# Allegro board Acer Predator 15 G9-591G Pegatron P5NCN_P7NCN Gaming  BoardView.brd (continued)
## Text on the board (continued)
User.45: list("[Package] TOP" "335.Pkg to Pkg Spacing" "0 MIL [PACKAGE_HEIGHT_MIN]" "2 MIL" "-2.00 MIL" "DRC ERROR CLASS/PACKAGE_TOP" "[Shape] Package Geometry/Place_Bound_Top ((-864.6 4046.87) (-777.58 4231.53))" "[Shape] Package Geometry/Place_Bound_Top ((-833.59 4161.7) (-808.59 4186.7))" list(-833.590000 4161.700000) nil)@@@list("kelly1_pan" "2015/09/04 16:11:31" nil "P143000035-PC" "n3-p5-p7ncn.20")@@@list("jennifer_hsu" "2015/09/07 11:49:47" nil "P143000039-PC" "n3-p5-p7ncn.20") | list("[Package] TOP" "336.Pkg to Pkg Spacing" "0 MIL [PACKAGE_HEIGHT_MIN]" "2 MIL" "-2.00 MIL" "DRC ERROR CLASS/PACKAGE_TOP" "[Shape] Package Geometry/Place_Bound_Top ((-864.6 4046.87) (-777.58 4231.53))" "[Shape] Package Geometry/Place_Bound_Top ((-833.59 4091.7) (-808.59 4116.7))" list(-833.590000 4091.700000) nil)@@@list("kelly1_pan" "2015/09/04 16:11:32" nil "P143000035-PC" "n3-p5-p7ncn.20")@@@list("jennifer_hsu" "2015/09/07 11:49:48" nil "P143000039-PC" "n3-p5-p7ncn.20") | list("[Package] BOTTOM" "370.Pkg to Place Keepin Spacing" "0 MIL [NONE]" "0 MIL" "0.00 MIL" "DRC ERROR CLASS/PACKAGE_BOTTOM" "[Shape] Package Keepin/All ((-897.01 -353.7) (9751.34 6916.7))" "[Shape] Package Geometry/Place_Bound_Bottom ((-826.78 3556.76) (-495.92 3746.25))" list(-824.120000 3556.760000) nil)@@@list("kelly1_pan" "2015/09/04 16:12:11" nil "P143000035-PC" "n3-p5-p7ncn.20")@@@list("jennifer_hsu" "2015/09/07 11:50:24" nil "P143000039-PC" "n3-p5-p7ncn.20") | list("[Electrical] ALL" "240.Propagation Delay" "::0.00 MIL:8000.00 MIL [PROPAGATION_DELAY]" "10131.06 MIL" "" "DRC ERROR CLASS/ALL" "[PinPair] <uTiL>cId71<uTiL>.L2:<uTiL>cId4738<uTiL>.40 ((5552.76 2057.63) (-807.76 4797.41))" " " list(-807.760000 4797.410000) nil)@@@list("kelly1_pan" "2015/09/04 14:32:31" nil "P143000035-PC" "n3-p5-p7ncn.20")@@@list("jennifer_hsu" "2015/09/07 11:47:53" nil "P143000039-PC" "n3-p5-p7ncn.20") | list("[Electrical] ALL" "241.Propagation Delay" "::0.00 MIL:8000.00 MIL [PROPAGATION_DELAY]" "10129.08 MIL" "" "DRC ERROR CLASS/ALL" "[PinPair] <uTiL>cId71<uTiL>.L1:<uTiL>cId4738<uTiL>.42 ((5552.76 2077.63) (-807.76 4777.72))" " " list(-807.760000 4777.720000) nil)@@@list("kelly1_pan" "2015/09/04 14:32:32" nil "P143000035-PC" "n3-p5-p7ncn.20")@@@list("jennifer_hsu" "2015/09/07 11:47:54" nil "P143000039-PC" "n3-p5-p7ncn.20") | list("[Electrical] ALL" "242.Propagation Delay" "::2000 mil:13000 mil [PROPAGATION_DELAY]" "13093.22 MIL" "" "DRC ERROR CLASS/ALL" "[PinPair] <uTiL>cId71<uTiL>.BC29:<uTiL>cId4738<uTiL>.60 ((6170.9 1543.34) (-807.76 4600.56))" " " list(-807.760000 4600.560000) nil)@@@list("kelly1_pan" "2015/09/04 14:32:34" nil "P143000035-PC" "n3-p5-p7ncn.20")@@@list("jennifer_hsu" "2015/09/07 11:47:55" nil "P143000039-PC" "n3-p5-p7ncn.20") | list("[Package] TOP" "337.Pkg to Pkg Spacing" "0 MIL [PACKAGE_HEIGHT_MIN]" "2 MIL" "-2.00 MIL" "DRC ERROR CLASS/PACKAGE_TOP" "[Shape] Package Geometry/Place_Bound_Top ((-787.6 5619.96) (-432.4 5903.82))" "[Shape] Package Geometry/Place_Bound_Top ((-692.5 5729.39) (-667.5 5754.39))" list(-787.600000 5741.890000) nil)@@@list("kelly1_pan" "2015/09/04 16:11:34" nil "P143000035-PC" "n3-p5-p7ncn.20")@@@list("jennifer_hsu" "2015/09/07 11:49:48" nil "P143000039-PC" "n3-p5-p7ncn.20") | list("[Package] BOTTOM" "376.Pkg to Place Keepin Spacing" "0 MIL [NONE]" "153.7 MIL" "-153.70 MIL" "DRC ERROR CLASS/PACKAGE_BOTTOM" "[Shape] Package Keepin/All ((-897.01 -353.7) (9751.34 6916.7))" "[Shape] Package Geometry/Place_Bound_Bottom ((-835.12 7070.4) (-675.12 7230.4))" list(-755.120000 6916.700000) nil)@@@list("kelly1_pan" "2015/09/04 16:12:17" nil "P143000035-PC" "n3-p5-p7ncn.20")@@@list("jennifer_hsu" "2015/09/07 11:50:29" nil "P143000039-PC" "n3-p5-p7ncn.20") | list("[Package] TOP" "315.Pkg to Place Keepin Spacing" "0 MIL [NONE]" "153.7 MIL" "-153.70 MIL" "DRC ERROR CLASS/PACKAGE_TOP" "[Shape] Package Keepin/All ((-897.01 -353.7) (9751.34 6916.7))" "[Shape] Package Geometry/Place_Bound_Top ((-835.12 7070.4) (-675.12 7230.4))" list(-755.120000 6916.700000) nil)@@@list("kelly1_pan" "2015/09/04 16:11:04" nil "P143000035-PC" "n3-p5-p7ncn.20")@@@list("jennifer_hsu" "2015/09/07 11:49:22" nil "P143000039-PC" "n3-p5-p7ncn.20") | list("[Electrical] ALL" "252.Propagation Delay" "::2500.00 MIL:5000.00 MIL [PROPAGATION_DELAY]" "8112.74 MIL" "" "DRC ERROR CLASS/ALL" "[PinPair] <uTiL>cId71<uTiL>.E11:<uTiL>cId4003<uTiL>.43 ((5430.14 1895.26) (-557.0 2864.15))" " " list(-557.000000 2864.150000) nil)@@@list("kelly1_pan" "2015/09/04 14:32:48" nil "P143000035-PC" "n3-p5-p7ncn.20")@@@list("jennifer_hsu" "2015/09/07 11:48:06" nil "P143000039-PC" "n3-p5-p7ncn.20") | list("[Electrical] ALL" "253.Propagation Delay" "::2500.00 MIL:5000.00 MIL [PROPAGATION_DELAY]" "8112.59 MIL" "" "DRC ERROR CLASS/ALL" "[PinPair] <uTiL>cId71<uTiL>.G11:<uTiL>cId4003<uTiL>.42 ((5465.09 1889.57) (-557.0 2844.47))" " " list(-557.000000 2844.470000) nil)@@@list("kelly1_pan" "2015/09/04 16:03:03" nil "P143000035-PC" "n3-p5-p7ncn.20")@@@list("jennifer_hsu" "2015/09/07 11:48:07" nil "P143000039-PC" "n3-p5-p7ncn.20") | list("[Electrical] ALL" "256.Propagation Delay" "::2500.00 MIL:5000.00 MIL [PROPAGATION_DELAY]" "7785.26 MIL" "" "DRC ERROR CLASS/ALL" "[PinPair] <uTiL>cId71<uTiL>.B10:<uTiL>cId4003<uTiL>.34 ((5377.06 1916.63) (-557.0 2686.99))" " " list(-557.000000 2686.990000) nil)@@@list("kelly1_pan" "2015/09/04 16:03:08" nil "P143000035-PC" "n3-p5-p7ncn.20")@@@list("jennifer_hsu" "2015/09/07 11:48:10" nil "P143000039-PC" "n3-p5-p7ncn.20") | list("[Electrical] ALL" "258.Propagation Delay" "::2500.00 MIL:5000.00 MIL [PROPAGATION_DELAY]" "7784.38 MIL" "" "DRC ERROR CLASS/ALL" "[PinPair] <uTiL>cId71<uTiL>.A9:<uTiL>cId4003<uTiL>.33 ((5354.26 1921.65) (-557.0 2667.3))" " " list(-557.000000 2667.300000) nil)@@@list("kelly1_pan" "2015/09/04 16:03:11" nil "P143000035-PC" "n3-p5-p7ncn.20")@@@list("jennifer_hsu" "2015/09/07 11:48:12" nil "P143000039-PC" "n3-p5-p7ncn.20") | list("[Electrical] ALL" "196.Propagation Delay" "::2500.00 MIL:5000.00 MIL [PROPAGATION_DELAY]" "7402.96 MIL" "" "DRC ERROR CLASS/ALL" "[PinPair] <uTiL>cId71<uTiL>.C13:<uTiL>cId4003<uTiL>.31 ((5389.1 1849.94) (-557.0 2627.93))" " " list(-557.000000 2627.930000) nil)@@@list("kelly1_pan" "2015/09/04 14:31:25" nil "P143000035-PC" "n3-p5-p7ncn.20")@@@list("jennifer_hsu" "2015/09/07 11:47:07" nil "P143000039-PC" "n3-p5-p7ncn.20") | list("[Electrical] ALL" "195.Propagation Delay" "::2500.00 MIL:5000.00 MIL [PROPAGATION_DELAY]" "7404.26 MIL" "" "DRC ERROR CLASS/ALL" "[PinPair] <uTiL>cId71<uTiL>.D13:<uTiL>cId4003<uTiL>.30 ((5409.1 1850.94) (-557.0 2608.25))" " " list(-557.000000 2608.250000) nil)@@@list("kelly1_pan" "2015/09/04 14:31:24" nil "P143000035-PC" "n3-p5-p7ncn.20")@@@list("jennifer_hsu" "2015/09/07 11:47:06" nil "P143000039-PC" "n3-p5-p7ncn.20") | list("[Electrical] ALL" "286.Propagation Delay" "::0.00 MIL:5000.00 MIL [PROPAGATION_DELAY]" "7752.66 MIL" "" "DRC ERROR CLASS/ALL" "[PinPair] <uTiL>cId71<uTiL>.AE1:<uTiL>cId4003<uTiL>.28 ((5821.26 2077.63) (-557.0 2568.88))" " " list(-557.000000 2568.880000) nil)@@@list("kelly1_pan" "2015/09/04 16:10:29" nil "P143000035-PC" "n3-p5-p7ncn.20")@@@list("jennifer_hsu" "2015/09/07 11:48:42" nil "P143000039-PC" "n3-p5-p7ncn.20") | list("[Electrical] ALL" "287.Propagation Delay" "::0.00 MIL:5000.00 MIL [PROPAGATION_DELAY]" "7756.98 MIL" "" "DRC ERROR CLASS/ALL" "[PinPair] <uTiL>cId71<uTiL>.AE2:<uTiL>cId4003<uTiL>.27 ((5821.26 2057.63) (-557.0 2549.19))" " " list(-557.000000 2549.190000) nil)@@@list("kelly1_pan" "2015/09/04 16:10:30" nil "P143000035-PC" "n3-p5-p7ncn.20")@@@list("jennifer_hsu" "2015/09/07 11:48:43" nil "P143000039-PC" "n3-p5-p7ncn.20") | list("[Package] TOP" "338.Pkg to Pkg Spacing" "0 MIL [PACKAGE_HEIGHT_MIN]" "2 MIL" "-2.00 MIL" "DRC ERROR CLASS/PACKAGE_TOP" "[Shape] Package Geometry/Place_Bound_Top ((-787.6 5619.96) (-432.4 5903.82))" "[Shape] Package Geometry/Place_Bound_Top ((-552.5 5719.39) (-527.5 5744.39))" list(-432.400000 5731.890000) nil)@@@list("kelly1_pan" "2015/09/04 16:11:35" nil "P143000035-PC" "n3-p5-p7ncn.20")@@@list("jennifer_hsu" "2015/09/07 11:49:49" nil "P143000039-PC" "n3-p5-p7ncn.20") | list("[Package] TOP" "309.Pkg to Place Keepin Spacing" "0 MIL [NONE]" "0 MIL" "0.00 MIL" "DRC ERROR CLASS/PACKAGE_TOP" "[Shape] Package Keepin/All ((-897.01 -353.7) (9751.34 6916.7))" "[Shape] Package Geometry/Place_Bound_Top ((-242.29 6641.71) (92.71 6956.71))" list(-242.290000 6916.700000) nil)@@@list("kelly1_pan" "2015/09/04 16:10:55" nil "P143000035-PC" "n3-p5-p7ncn.20")@@@list("jennifer_hsu" "2015/09/07 11:49:18" nil "P143000039-PC" "n3-p5-p7ncn.20") | list("[Package] BOTTOM" "363.Pkg to Place Keepin Spacing" "0 MIL [NONE]" "0 MIL" "0.00 MIL" "DRC ERROR CLASS/PACKAGE_BOTTOM" "[Shape] Package Keepin/All ((-897.01 -353.7) (9751.34 6916.7))" "[Shape] Package Geometry/Place_Bound_Bottom ((-232.29 6641.71) (82.71 6956.71))" list(-179.680000 6916.700000) nil)@@@list("kelly1_pan" "2015/09/04 16:12:04" nil "P143000035-PC" "n3-p5-p7ncn.20")@@@list("jennifer_hsu" "2015/09/07 11:50:17" nil "P143000039-PC" "n3-p5-p7ncn.20") | list("[Package] BOTTOM" "355.Pkg to Place Keepin Spacing" "0 MIL [NONE]" "0 MIL" "0.00 MIL" "DRC ERROR CLASS/PACKAGE_BOTTOM" "[Shape] Package Keepin/All ((-897.01 -353.7) (9751.34 6916.7))" "[Shape] Package Geometry/Place_Bound_Bottom ((-449.01 143.5) (19.1 1506.1))" list(-117.480000 143.500000) nil)@@@list("kelly1_pan" "2015/09/04 16:11:56" nil "P143000035-PC" "n3-p5-p7ncn.20")@@@list("jennifer_hsu" "2015/09/07 11:50:06" nil "P143000039-PC" "n3-p5-p7ncn.20") | list("[Package] BOTTOM" "375.Pkg to Place Keepin Spacing" "0 MIL [NONE]" "576.2 MIL" "-576.20 MIL" "DRC ERROR CLASS/PACKAGE_BOTTOM" "[Shape] Package Keepin/All ((-897.01 -353.7) (9751.34 6916.7))" "[Shape] Package Geometry/Place_Bound_Bottom ((-835.12 -588.66) (-675.12 -428.66))" list(-117.480000 -353.700000) nil)@@@list("kelly1_pan" "2015/09/04 16:12:16" nil "P143000035-PC" "n3-p5-p7ncn.20")@@@list("jennifer_hsu" "2015/09/07 11:50:28" nil "P143000039-PC" "n3-p5-p7ncn.20") | list("[Package] TOP" "314.Pkg to Place Keepin Spacing" "0 MIL [NONE]" "576.2 MIL" "-576.20 MIL" "DRC ERROR CLASS/PACKAGE_TOP" "[Shape] Package Keepin/All ((-897.01 -353.7) (9751.34 6916.7))" "[Shape] Package Geometry/Place_Bound_Top ((-835.12 -588.66) (-675.12 -428.66))" list(-117.480000 -353.700000) nil)@@@list("kelly1_pan" "2015/09/04 16:11:03" nil "P143000035-PC" "n3-p5-p7ncn.20")@@@list("jennifer_hsu" "2015/09/07 11:49:21" nil "P143000039-PC" "n3-p5-p7ncn.20") | list("[Package] TOP" "319.Pkg to Place Keepin Spacing" "0 MIL [NONE]" "138.64 MIL" "-138.64 MIL" "DRC ERROR CLASS/PACKAGE_TOP" "[Shape] Package Keepin/All ((-897.01 -353.7) (9751.34 6916.7))" "[Shape] Package Geometry/Place_Bound_Top ((-200.18 7055.34) (-10.06 7245.46))" list(-105.130000 6916.700000) nil)@@@list("kelly1_pan" "2015/09/04 16:11:09" nil "P143000035-PC" "n3-p5-p7ncn.20")@@@list("jennifer_hsu" "2015/09/07 11:49:25" nil "P143000039-PC" "n3-p5-p7ncn.20") | list("[Package] TOP" "339.Pkg to Pkg Spacing" "0 MIL [PACKAGE_HEIGHT_MIN]" "2 MIL" "-2.00 MIL" "DRC ERROR CLASS/PACKAGE_TOP" "[Shape] Package Geometry/Place_Bound_Top ((-171.93 5764.29) (111.93 6119.49))" "[Shape] Package Geometry/Place_Bound_Top ((-42.5 5999.39) (-17.5 6024.39))" list(-30.000000 6119.490000) nil)@@@list("kelly1_pan" "2015/09/04 16:11:36" nil "P143000035-PC" "n3-p5-p7ncn.20")@@@list("jennifer_hsu" "2015/09/07 11:49:52" nil "P143000039-PC" "n3-p5-p7ncn.20") | list("[Package] TOP" "340.Pkg to Pkg Spacing" "0 MIL [PACKAGE_HEIGHT_MIN]" "2 MIL" "-2.00 MIL" "DRC ERROR CLASS/PACKAGE_TOP" "[Shape] Package Geometry/Place_Bound_Top ((-171.93 5764.29) (111.93 6119.49))" "[Shape] Package Geometry/Place_Bound_Top ((-42.5 5859.39) (-17.5 5884.39))" list(-30.000000 5764.290000) nil)@@@list("kelly1_pan" "2015/09/04 16:11:37" nil "P143000035-PC" "n3-p5-p7ncn.20")@@@list("jennifer_hsu" "2015/09/07 11:49:53" nil "P143000039-PC" "n3-p5-p7ncn.20") | list("[Package] BOTTOM" "380.Pkg to Place Keepin Spacing" "0 MIL [NONE]" "139.98 MIL" "-139.98 MIL" "DRC ERROR CLASS/PACKAGE_BOTTOM" "[Shape] Package Keepin/All ((-897.01 -353.7) (9751.34 6916.7))" "[Shape] Package Geometry/Place_Bound_Bottom ((-0.18 7055.34) (189.94 7245.46))" list(69.860000 6916.700000) nil)@@@list("kelly1_pan" "2015/09/04 16:12:21" nil "P143000035-PC" "n3-p5-p7ncn.20")@@@list("jennifer_hsu" "2015/09/07 11:50:31" nil "P143000039-PC" "n3-p5-p7ncn.20") | list("[Electrical] ALL" "259.Diffpair Max Uncoupled Length" "200 MIL [DIFFP_UNCOUPLED_LENGTH]" "210.69 MIL" "-10.69 MIL" "DRC ERROR CLASS/ALL" "[PinPair] <uTiL>cId3011<uTiL>.32:<uTiL>cId3020<uTiL>.BL3 ((691.93 2649.6) (40.5 4582.15))" "[PinPair] <uTiL>cId3011<uTiL>.34:<uTiL>cId3020<uTiL>.BK3 ((711.62 2649.6) (71.5 4582.15))" list(71.500000 4582.150000) nil)@@@list("kelly1_pan" "2015/09/04 16:03:12" nil "P143000035-PC" "n3-p5-p7ncn.20")@@@list("jennifer_hsu" "2015/09/07 11:48:13" nil "P143000039-PC" "n3-p5-p7ncn.20") | list("[Package] BOTTOM" "382.Pkg to Place Keepin Spacing" "0 MIL [NONE]" "312.91 MIL" "-312.91 MIL" "DRC ERROR CLASS/PACKAGE_BOTTOM" "[Shape] Package Keepin/All ((-897.01 -353.7) (9751.34 6916.7))" "[Shape] Package Geometry/Place_Bound_Bottom ((399.82 -603.72) (589.94 -413.6))" list(117.480000 -353.700000) nil)@@@list("kelly1_pan" "2015/09/04 16:12:23" nil "P143000035-PC" "n3-p5-p7ncn.20")@@@list("jennifer_hsu" "2015/09/07 11:50:34" nil "P143000039-PC" "n3-p5-p7ncn.20") | list("[Package] TOP" "321.Pkg to Place Keepin Spacing" "0 MIL [NONE]" "140.49 MIL" "-140.49 MIL" "DRC ERROR CLASS/PACKAGE_TOP" "[Shape] Package Keepin/All ((-897.01 -353.7) (9751.34 6916.7))" "[Shape] Package Geometry/Place_Bound_Top ((199.82 -603.72) (389.94 -413.6))" list(117.480000 -353.700000) nil)@@@list("kelly1_pan" "2015/09/04 16:11:12" nil "P143000035-PC" "n3-p5-p7ncn.20")@@@list("jennifer_hsu" "2015/09/07 11:49:27" nil "P143000039-PC" "n3-p5-p7ncn.20") | list("[Electrical] ALL" "263.Diffpair Max Uncoupled Length" "200 MIL [DIFFP_UNCOUPLED_LENGTH]" "204.79 MIL" "-4.79 MIL" "DRC ERROR CLASS/ALL" "[PinPair] <uTiL>cId3011<uTiL>.55:<uTiL>cId3020<uTiL>.BF3 ((918.31 2326.76) (168.5 4582.15))" "[PinPair] <uTiL>cId3011<uTiL>.53:<uTiL>cId3020<uTiL>.BG3 ((898.62 2326.76) (139.5 4582.15))" list(139.500000 4582.150000) nil)@@@list("kelly1_pan" "2015/09/04 16:09:31" nil "P143000035-PC" "n3-p5-p7ncn.20")@@@list("jennifer_hsu" "2015/09/07 11:48:17" nil "P143000039-PC" "n3-p5-p7ncn.20") | list("[Package] BOTTOM" "350.Pkg to Pkg Spacing" "0 MIL [PACKAGE_HEIGHT_MIN]" "157.48 MIL" "-157.48 MIL" "DRC ERROR CLASS/PACKAGE_BOTTOM" "[Shape] Package Geometry/Place_Bound_Bottom ((74.61 1807.82) (3169.49 2848.62))" "[Shape] Package Geometry/Place_Bound_Bottom ((-70.85 1910.6) (165.45 2119.66))" list(159.250000 1910.600000) nil)@@@list("kelly1_pan" "2015/09/04 16:11:50" nil "P143000035-PC" "n3-p5-p7ncn.20")@@@list("jennifer_hsu" "2015/09/07 11:50:00" nil "P143000039-PC" "n3-p5-p7ncn.20") | list("[Package] TOP" "341.Pkg to Pkg Spacing" "0 MIL [PACKAGE_HEIGHT_MIN]" "2 MIL" "-2.00 MIL" "DRC ERROR CLASS/PACKAGE_TOP" "[Shape] Package Geometry/Place_Bound_Top ((192.4 5964.96) (547.6 6248.82))" "[Shape] Package Geometry/Place_Bound_Top ((286.7 6125.99) (311.7 6150.99))" list(192.400000 6138.490000) nil)@@@list("kelly1_pan" "2015/09/04 16:11:38" nil "P143000035-PC" "n3-p5-p7ncn.20")@@@list("jennifer_hsu" "2015/09/07 11:49:53" nil "P143000039-PC" "n3-p5-p7ncn.20") | list("[Electrical] ALL" "283.Diffpair Max Uncoupled Length" "200 MIL [DIFFP_UNCOUPLED_LENGTH]" "245.81 MIL" "-45.81 MIL" "DRC ERROR CLASS/ALL" "[PinPair] <uTiL>cId3011<uTiL>.76:<uTiL>cId3020<uTiL>.BC3 ((1125.0 2649.6) (267.5 4582.15))" "[PinPair] <uTiL>cId3011<uTiL>.74:<uTiL>cId3020<uTiL>.BD3 ((1105.32 2649.6) (238.5 4582.15))" list(238.500000 4582.150000) nil)@@@list("kelly1_pan" "2015/09/04 16:10:24" nil "P143000035-PC" "n3-p5-p7ncn.20")@@@list("jennifer_hsu" "2015/09/07 11:48:39" nil "P143000039-PC" "n3-p5-p7ncn.20") | list("[Electrical] ALL" "281.Diffpair Phase Tolerance" "5 mil [DIFFP_PHASE_TOL]" "5.25 MIL" "" "DRC ERROR CLASS/ALL" "[PinPair] <uTiL>cId3011<uTiL>.74:<uTiL>cId3020<uTiL>.BD3 ((1105.32 2649.6) (238.5 4582.15))" "[PinPair] <uTiL>cId3011<uTiL>.76:<uTiL>cId3020<uTiL>.BC3 ((1125.0 2649.6) (267.5 4582.15))" list(267.500000 4582.150000) nil)@@@list("kelly1_pan" "2015/09/04 16:10:20" nil "P143000035-PC" "n3-p5-p7ncn.20")@@@list("jennifer_hsu" "2015/09/07 11:48:36" nil "P143000039-PC" "n3-p5-p7ncn.20") | list("[Electrical] ALL" "251.Relative Propagation Delay" "R_M_CHB_D3_CON1701:G:::0.00 MIL:32.00 MIL [RELATIVE_PROPAGATION_DELAY]" "32.58 MIL" "" "DRC ERROR CLASS/ALL" "[PinPair] <uTiL>cId3020<uTiL>.BB9:<uTiL>cId3009<uTiL>.76 ((291.67 4736.13) (1046.26 1854.33))" "[PinPair] <uTiL>cId3020<uTiL>.BB11:<uTiL>cId3009<uTiL>.84 ((291.67 4787.33) (1125.0 1854.33))" list(291.670000 4787.330000) nil)@@@list("kelly1_pan" "2015/09/04 14:32:47" nil "P143000035-PC" "n3-p5-p7ncn.20")@@@list("jennifer_hsu" "2015/09/07 11:48:05" nil "P143000039-PC" "n3-p5-p7ncn.20") | list("[Electrical] ALL" "255.Diffpair Phase Tolerance" "5 mil [DIFFP_PHASE_TOL]" "5.26 MIL" "" "DRC ERROR CLASS/ALL" "[PinPair] <uTiL>cId1850<uTiL>.13:<uTiL>cId3020<uTiL>.BP5 ((426.18 2649.62) (-36.84 4624.43))" "[PinPair] <uTiL>cId3020<uTiL>.BR5:<uTiL>cId1850<uTiL>.11 ((-61.74 4616.23) (406.5 2649.62))" list(406.500000 2649.620000) nil)@@@list("kelly1_pan" "2015/09/04 16:03:07" nil "P143000035-PC" "n3-p5-p7ncn.20")@@@list("jennifer_hsu" "2015/09/07 11:48:09" nil "P143000039-PC" "n3-p5-p7ncn.20") | list("[Package] TOP" "342.Pkg to Pkg Spacing" "0 MIL [PACKAGE_HEIGHT_MIN]" "2 MIL" "-2.00 MIL" "DRC ERROR CLASS/PACKAGE_TOP" "[Shape] Package Geometry/Place_Bound_Top ((192.4 5964.96) (547.6 6248.82))" "[Shape] Package Geometry/Place_Bound_Top ((421.7 6130.99) (446.7 6155.99))" list(434.200000 6248.820000) nil)@@@list("kelly1_pan" "2015/09/04 16:11:39" nil "P143000035-PC" "n3-p5-p7ncn.20")@@@list("jennifer_hsu" "2015/09/07 11:49:54" nil "P143000039-PC" "n3-p5-p7ncn.20") | list("[Electrical] ALL" "273.Relative Propagation Delay" "R_M_CHB_ADD:G::::200.00 MIL [RELATIVE_PROPAGATION_DELAY]" "200.42 MIL" "" "DRC ERROR CLASS/ALL" "[PinPair] <uTiL>cId3020<uTiL>.AL5:<uTiL>cId3009<uTiL>.131 ((634.5 4633.35) (1587.6 2177.17))" "[PinPair] <uTiL>cId3020<uTiL>.AN10:<uTiL>cId3009<uTiL>.122 ((579.67 4761.73) (1499.02 1854.33))" list(579.670000 4761.730000) nil)@@@list("kelly1_pan" "2015/09/04 16:10:05" nil "P143000035-PC" "n3-p5-p7ncn.20")@@@list("jennifer_hsu" "2015/09/07 11:48:28" nil "P143000039-PC" "n3-p5-p7ncn.20") | list("[Package] TOP" "343.Pkg to Pkg Spacing" "0 MIL [PACKAGE_HEIGHT_MIN]" "2 MIL" "-2.00 MIL" "DRC ERROR CLASS/PACKAGE_TOP" "[Shape] Package Geometry/Place_Bound_Top ((602.4 5959.96) (957.6 6243.82))" "[Shape] Package Geometry/Place_Bound_Top ((697.5 6109.39) (722.5 6134.39))" list(602.400000 6121.890000) nil)@@@list("kelly1_pan" "2015/09/04 16:11:40" nil "P143000035-PC" "n3-p5-p7ncn.20")@@@list("jennifer_hsu" "2015/09/07 11:49:55" nil "P143000039-PC" "n3-p5-p7ncn.20") | list("[Electrical] ALL" "279.Relative Propagation Delay" "R_M_CHB_ADD:G::::200.00 MIL [RELATIVE_PROPAGATION_DELAY]" "202.2 MIL" "" "DRC ERROR CLASS/ALL" "[PinPair] <uTiL>cId3020<uTiL>.AL5:<uTiL>cId3009<uTiL>.131 ((634.5 4633.35) (1587.6 2177.17))" "[PinPair] <uTiL>cId3020<uTiL>.AK5:<uTiL>cId3010<uTiL>.132 ((663.5 4633.35) (1676.19 2177.18))" list(663.500000 4633.350000) nil)@@@list("kelly1_pan" "2015/09/04 16:10:16" nil "P143000035-PC" "n3-p5-p7ncn.20")@@@list("jennifer_hsu" "2015/09/07 11:48:34" nil "P143000039-PC" "n3-p5-p7ncn.20") | list("[Electrical] ALL" "280.Diffpair Max Uncoupled Length" "200 MIL [DIFFP_UNCOUPLED_LENGTH]" "221.14 MIL" "-21.14 MIL" "DRC ERROR CLASS/ALL" "[PinPair] <uTiL>cId3011<uTiL>.138:<uTiL>cId3020<uTiL>.AK2 ((1735.24 2649.6) (663.5 4556.55))" "[PinPair] <uTiL>cId3011<uTiL>.140:<uTiL>cId3020<uTiL>.AK1 ((1754.92 2649.6) (663.5 4530.95))" list(663.500000 4530.950000) nil)@@@list("kelly1_pan" "2015/09/04 16:10:18" nil "P143000035-PC" "n3-p5-p7ncn.20")@@@list("jennifer_hsu" "2015/09/07 11:48:35" nil "P143000039-PC" "n3-p5-p7ncn.20") | list("[Electrical] ALL" "293.Diffpair Max Uncoupled Length" "200 MIL [DIFFP_UNCOUPLED_LENGTH]" "244.27 MIL" "-44.27 MIL" "DRC ERROR CLASS/ALL" "[PinPair] <uTiL>cId3020<uTiL>.BL9:<uTiL>cId3010<uTiL>.32 ((40.89 4753.93) (691.94 2177.18))" "[PinPair] <uTiL>cId3020<uTiL>.BJ9:<uTiL>cId3010<uTiL>.34 ((75.67 4736.13) (711.63 2177.18))" list(711.630000 2177.180000) nil)@@@list("kelly1_pan" "2015/09/04 16:10:38" nil "P143000035-PC" "n3-p5-p7ncn.20")@@@list("jennifer_hsu" "2015/09/07 11:48:57" nil "P143000039-PC" "n3-p5-p7ncn.20") | list("[Electrical] ALL" "278.Relative Propagation Delay" "R_M_CHB_ADD:G::::200.00 MIL [RELATIVE_PROPAGATION_DELAY]" "238.79 MIL" "" "DRC ERROR CLASS/ALL" "[PinPair] <uTiL>cId3020<uTiL>.AL5:<uTiL>cId3009<uTiL>.131 ((634.5 4633.35) (1587.6 2177.17))" "[PinPair] <uTiL>cId3020<uTiL>.AH11:<uTiL>cId3010<uTiL>.151 ((723.67 4787.33) (1941.94 1854.34))" list(723.670000 4787.330000) nil)@@@list("kelly1_pan" "2015/09/04 16:10:13" nil "P143000035-PC" "n3-p5-p7ncn.20")@@@list("jennifer_hsu" "2015/09/07 11:48:33" nil "P143000039-PC" "n3-p5-p7ncn.20") | list("[Electrical] ALL" "290.Relative Propagation Delay" "R_M_CHB_D4_CON1701:G:::0.00 MIL:19.00 MIL [RELATIVE_PROPAGATION_DELAY]" "22.82 MIL" "" "DRC ERROR CLASS/ALL" "[PinPair] <uTiL>cId3020<uTiL>.AA9:<uTiL>cId3009<uTiL>.179 ((939.67 4736.13) (2138.78 2177.17))" "[PinPair] <uTiL>cId3020<uTiL>.AC8:<uTiL>cId3009<uTiL>.169 ((903.67 4710.53) (2040.36 2177.17))" list(903.670000 4710.530000) nil)@@@list("kelly1_pan" "2015/09/04 16:10:34" nil "P143000035-PC" "n3-p5-p7ncn.20")@@@list("jennifer_hsu" "2015/09/07 11:48:46" nil "P143000039-PC" "n3-p5-p7ncn.20") | list("[Package] TOP" "344.Pkg to Pkg Spacing" "0 MIL [PACKAGE_HEIGHT_MIN]" "2 MIL" "-2.00 MIL" "DRC ERROR CLASS/PACKAGE_TOP" "[Shape] Package Geometry/Place_Bound_Top ((602.4 5959.96) (957.6 6243.82))" "[Shape] Package Geometry/Place_Bound_Top ((837.5 6109.39) (862.5 6134.39))" list(957.600000 6121.890000) nil)@@@list("kelly1_pan" "2015/09/04 16:11:41" nil "P143000035-PC" "n3-p5-p7ncn.20")@@@list("jennifer_hsu" "2015/09/07 11:49:56" nil "P143000039-PC" "n3-p5-p7ncn.20") | list("[Electrical] ALL" "268.Relative Propagation Delay" "R_M_CHA_D3_CON1601:G:::0.00 MIL:28.00 MIL [RELATIVE_PROPAGATION_DELAY]" "45.67 MIL" "" "DRC ERROR CLASS/ALL" "[PinPair] <uTiL>cId1850<uTiL>.76:<uTiL>cId3020<uTiL>.BC3 ((1046.26 2326.78) (267.5 4582.15))" "[PinPair] <uTiL>cId1850<uTiL>.67:<uTiL>cId3020<uTiL>.BD5 ((957.68 2649.62) (238.5 4633.35))" list(957.680000 2649.620000) nil)@@@list("kelly1_pan" "2015/09/04 16:09:37" nil "P143000035-PC" "n3-p5-p7ncn.20")@@@list("jennifer_hsu" "2015/09/07 11:48:23" nil "P143000039-PC" "n3-p5-p7ncn.20") | list("[Electrical] ALL" "265.Relative Propagation Delay" "R_M_CHA_D3_CON1601:G:::0.00 MIL:19.00 MIL [RELATIVE_PROPAGATION_DELAY]" "23.17 MIL" "" "DRC ERROR CLASS/ALL" "[PinPair] <uTiL>cId1850<uTiL>.76:<uTiL>cId3020<uTiL>.BC3 ((1046.26 2326.78) (267.5 4582.15))" "[PinPair] <uTiL>cId1850<uTiL>.71:<uTiL>cId3020<uTiL>.BD4 ((997.05 2649.62) (238.5 4607.75))" list(997.050000 2649.620000) nil)@@@list("kelly1_pan" "2015/09/04 16:09:33" nil "P143000035-PC" "n3-p5-p7ncn.20")@@@list("jennifer_hsu" "2015/09/07 11:48:19" nil "P143000039-PC" "n3-p5-p7ncn.20") | list("[Electrical] ALL" "266.Relative Propagation Delay" "R_M_CHA_D3_CON1601:G:::0.00 MIL:1.00 MIL [RELATIVE_PROPAGATION_DELAY]" "1.85 MIL" "" "DRC ERROR CLASS/ALL" "[PinPair] <uTiL>cId1850<uTiL>.76:<uTiL>cId3020<uTiL>.BC3 ((1046.26 2326.78) (267.5 4582.15))" "[PinPair] <uTiL>cId1850<uTiL>.74:<uTiL>cId3020<uTiL>.BD3 ((1026.58 2326.78) (238.5 4582.15))" list(1026.580000 2326.780000) nil)@@@list("kelly1_pan" "2015/09/04 16:09:35" nil "P143000035-PC" "n3-p5-p7ncn.20")@@@list("jennifer_hsu" "2015/09/07 11:48:20" nil "P143000039-PC" "n3-p5-p7ncn.20") | list("[Electrical] ALL" "270.Relative Propagation Delay" "R_M_CHA_D3_CON1600:G:::0.00 MIL:19.00 MIL [RELATIVE_PROPAGATION_DELAY]" "21.48 MIL" "" "DRC ERROR CLASS/ALL" "[PinPair] <uTiL>cId3011<uTiL>.76:<uTiL>cId3020<uTiL>.BC3 ((1125.0 2649.6) (267.5 4582.15))" "[PinPair] <uTiL>cId3011<uTiL>.67:<uTiL>cId3020<uTiL>.BD2 ((1036.42 2326.76) (238.5 4556.55))" list(1036.420000 2326.760000) nil)@@@list("kelly1_pan" "2015/09/04 16:10:01" nil "P143000035-PC" "n3-p5-p7ncn.20")@@@list("jennifer_hsu" "2015/09/07 11:48:25" nil "P143000039-PC" "n3-p5-p7ncn.20") | list("[Electrical] ALL" "254.Diffpair Max Uncoupled Length" "200 MIL [DIFFP_UNCOUPLED_LENGTH]" "210.43 MIL" "-10.43 MIL" "DRC ERROR CLASS/ALL" "[PinPair] <uTiL>cId3020<uTiL>.V3:<uTiL>cId3011<uTiL>.200 ((1030.5 4582.15) (2424.22 2649.6))" "[PinPair] <uTiL>cId3020<uTiL>.U3:<uTiL>cId3011<uTiL>.198 ((1059.5 4582.15) (2404.53 2649.6))" list(1059.500000 4582.150000) nil)@@@list("kelly1_pan" "2015/09/04 16:03:04" nil "P143000035-PC" "n3-p5-p7ncn.20")@@@list("jennifer_hsu" "2015/09/07 11:48:08" nil "P143000039-PC" "n3-p5-p7ncn.20") | list("[Electrical] ALL" "271.Relative Propagation Delay" "R_M_CHA_D3_CON1600:G:::0.00 MIL:34.00 MIL [RELATIVE_PROPAGATION_DELAY]" "39.62 MIL" "" "DRC ERROR CLASS/ALL" "[PinPair] <uTiL>cId3011<uTiL>.76:<uTiL>cId3020<uTiL>.BC3 ((1125.0 2649.6) (267.5 4582.15))" "[PinPair] <uTiL>cId3011<uTiL>.70:<uTiL>cId3020<uTiL>.BD4 ((1065.95 2649.6) (238.5 4607.75))" list(1065.950000 2649.600000) nil)@@@list("kelly1_pan" "2015/09/04 16:10:02" nil "P143000035-PC" "n3-p5-p7ncn.20")@@@list("jennifer_hsu" "2015/09/07 11:48:26" nil "P143000039-PC" "n3-p5-p7ncn.20") | list("[Electrical] ALL" "264.Relative Propagation Delay" "R_M_CHA_D3_CON1601:G:::0.00 MIL:35.00 MIL [RELATIVE_PROPAGATION_DELAY]" "50.63 MIL" "" "DRC ERROR CLASS/ALL" "[PinPair] <uTiL>cId1850<uTiL>.76:<uTiL>cId3020<uTiL>.BC3 ((1046.26 2326.78) (267.5 4582.15))" "[PinPair] <uTiL>cId1850<uTiL>.80:<uTiL>cId3020<uTiL>.BC1 ((1085.63 2326.78) (267.5 4530.95))" list(1085.630000 2326.780000) nil)@@@list("kelly1_pan" "2015/09/04 16:09:32" nil "P143000035-PC" "n3-p5-p7ncn.20")@@@list("jennifer_hsu" "2015/09/07 11:48:18" nil "P143000039-PC" "n3-p5-p7ncn.20") | list("[Electrical] ALL" "269.Relative Propagation Delay" "R_M_CHA_D3_CON1600:G:::0.00 MIL:1.00 MIL [RELATIVE_PROPAGATION_DELAY]" "5.25 MIL" "" "DRC ERROR CLASS/ALL" "[PinPair] <uTiL>cId3011<uTiL>.76:<uTiL>cId3020<uTiL>.BC3 ((1125.0 2649.6) (267.5 4582.15))" "[PinPair] <uTiL>cId3011<uTiL>.74:<uTiL>cId3020<uTiL>.BD3 ((1105.32 2649.6) (238.5 4582.15))" list(1105.320000 2649.600000) nil)@@@list("kelly1_pan" "2015/09/04 16:10:00" nil "P143000035-PC" "n3-p5-p7ncn.20")@@@list("jennifer_hsu" "2015/09/07 11:48:24" nil "P143000039-PC" "n3-p5-p7ncn.20") | list("[Electrical] ALL" "267.Relative Propagation Delay" "R_M_CHA_D3_CON1601:G:::0.00 MIL:40.00 MIL [RELATIVE_PROPAGATION_DELAY]" "46.33 MIL" "" "DRC ERROR CLASS/ALL" "[PinPair] <uTiL>cId1850<uTiL>.76:<uTiL>cId3020<uTiL>.BC3 ((1046.26 2326.78) (267.5 4582.15))" "[PinPair] <uTiL>cId1850<uTiL>.84:<uTiL>cId3020<uTiL>.BC2 ((1125.0 2326.78) (267.5 4556.55))" list(1125.000000 2326.780000) nil)@@@list("kelly1_pan" "2015/09/04 16:09:36" nil "P143000035-PC" "n3-p5-p7ncn.20")@@@list("jennifer_hsu" "2015/09/07 11:48:22" nil "P143000039-PC" "n3-p5-p7ncn.20") | list("[Electrical] ALL" "272.Relative Propagation Delay" "R_M_CHA_D3_CON1600:G:::0.00 MIL:19.00 MIL [RELATIVE_PROPAGATION_DELAY]" "24.03 MIL" "" "DRC ERROR CLASS/ALL" "[PinPair] <uTiL>cId3011<uTiL>.76:<uTiL>cId3020<uTiL>.BC3 ((1125.0 2649.6) (267.5 4582.15))" "[PinPair] <uTiL>cId3011<uTiL>.79:<uTiL>cId3020<uTiL>.BC1 ((1154.53 2326.76) (267.5 4530.95))" list(1154.530000 2326.760000) nil)@@@list("kelly1_pan" "2015/09/04 16:10:03" nil "P143000035-PC" "n3-p5-p7ncn.20")@@@list("jennifer_hsu" "2015/09/07 11:48:27" nil "P143000039-PC" "n3-p5-p7ncn.20") | list("[Electrical] ALL" "257.Diffpair Max Uncoupled Length" "200 MIL [DIFFP_UNCOUPLED_LENGTH]" "212.57 MIL" "-12.57 MIL" "DRC ERROR CLASS/ALL" "[PinPair] <uTiL>cId3020<uTiL>.R3:<uTiL>cId3011<uTiL>.221 ((1129.5 4582.15) (2630.91 2326.76))" "[PinPair] <uTiL>cId3020<uTiL>.P3:<uTiL>cId3011<uTiL>.219 ((1158.5 4582.15) (2611.22 2326.76))" list(1158.500000 4582.150000) nil)@@@list("kelly1_pan" "2015/09/04 16:03:10" nil "P143000035-PC" "n3-p5-p7ncn.20")@@@list("jennifer_hsu" "2015/09/07 11:48:11" nil "P143000039-PC" "n3-p5-p7ncn.20") | list("[Package] BOTTOM" "391.Pkg to Pkg Spacing" "0 MIL [PACKAGE_HEIGHT_MIN]" "27.56 MIL" "-27.56 MIL" "DRC ERROR CLASS/PACKAGE_BOTTOM" "[Shape] Package Geometry/Place_Bound_Bottom ((1164.37 6433.7) (1235.63 6560.08))" "[Shape] Package Geometry/Place_Bound_Bottom ((1156.69 6435.87) (1243.31 6557.91))" list(1164.370000 6435.870000) nil)@@@list("kelly1_pan" "2015/09/04 16:12:32" nil "P143000035-PC" "n3-p5-p7ncn.20")@@@list("jennifer_hsu" "2015/09/07 11:50:41" nil "P143000039-PC" "n3-p5-p7ncn.20") | list("[Electrical] ALL" "294.Diffpair Max Uncoupled Length" "200 MIL [DIFFP_UNCOUPLED_LENGTH]" "218.7 MIL" "-18.70 MIL" "DRC ERROR CLASS/ALL" "[PinPair] <uTiL>cId3020<uTiL>.L9:<uTiL>cId3010<uTiL>.242 ((1263.67 4736.13) (2837.61 2177.18))" "[PinPair] <uTiL>cId3020<uTiL>.M9:<uTiL>cId3010<uTiL>.240 ((1227.67 4736.13) (2817.93 2177.18))" list(1227.670000 4736.130000) nil)@@@list("kelly1_pan" "2015/09/04 16:10:39" nil "P143000035-PC" "n3-p5-p7ncn.20")@@@list("jennifer_hsu" "2015/09/07 11:48:58" nil "P143000039-PC" "n3-p5-p7ncn.20") | list("[Electrical] ALL" "261.Diffpair Max Uncoupled Length" "200 MIL [DIFFP_UNCOUPLED_LENGTH]" "228.67 MIL" "-28.67 MIL" "DRC ERROR CLASS/ALL" "[PinPair] <uTiL>cId3020<uTiL>.M3:<uTiL>cId3011<uTiL>.242 ((1228.5 4582.15) (2837.6 2649.6))" "[PinPair] <uTiL>cId3020<uTiL>.L3:<uTiL>cId3011<uTiL>.240 ((1257.5 4582.15) (2817.92 2649.6))" list(1257.500000 4582.150000) nil)@@@list("kelly1_pan" "2015/09/04 16:09:27" nil "P143000035-PC" "n3-p5-p7ncn.20")@@@list("jennifer_hsu" "2015/09/07 11:48:15" nil "P143000039-PC" "n3-p5-p7ncn.20") | list("[Electrical] ALL" "262.Relative Propagation Delay" "R_M_CHA_D7_CON1600:G:::0.00 MIL:19.00 MIL [RELATIVE_PROPAGATION_DELAY]" "27.03 MIL" "" "DRC ERROR CLASS/ALL" "[PinPair] <uTiL>cId3020<uTiL>.M3:<uTiL>cId3011<uTiL>.242 ((1228.5 4582.15) (2837.6 2649.6))" "[PinPair] <uTiL>cId3020<uTiL>.L1:<uTiL>cId3011<uTiL>.246 ((1257.5 4530.95) (2876.97 2649.6))" list(1257.500000 4530.950000) nil)@@@list("kelly1_pan" "2015/09/04 16:09:28" nil "P143000035-PC" "n3-p5-p7ncn.20")@@@list("jennifer_hsu" "2015/09/07 11:48:16" nil "P143000039-PC" "n3-p5-p7ncn.20") | list("[Electrical] ALL" "200.Diffpair Max Uncoupled Length" "200 MIL [DIFFP_UNCOUPLED_LENGTH]" "212.04 MIL" "-12.04 MIL" "DRC ERROR CLASS/ALL" "[PinPair] <uTiL>cId3999<uTiL>.35:<uTiL>cId71<uTiL>.C32 ((1331.7 1332.69) (5397.06 1469.13))" "[PinPair] <uTiL>cId3999<uTiL>.37:<uTiL>cId71<uTiL>.B32 ((1331.7 1313.0) (5377.06 1469.13))" list(1331.700000 1313.000000) nil)@@@list("kelly1_pan" "2015/09/04 14:31:30" nil "P143000035-PC" "n3-p5-p7ncn.20")@@@list("jennifer_hsu" "2015/09/07 11:47:11" nil "P143000039-PC" "n3-p5-p7ncn.20") | list("[Electrical] ALL" "193.Propagation Delay" "::0.00 MIL:6500.00 MIL [PROPAGATION_DELAY]" "10429.89 MIL" "" "DRC ERROR CLASS/ALL" "[PinPair] <uTiL>cId5890<uTiL>.38:<uTiL>cId3020<uTiL>.H34 ((7323.11 1815.47) (1347.9 5476.91))" " " list(1347.900000 5476.910000) nil)@@@list("kelly1_pan" "2015/09/04 14:31:22" nil "P143000035-PC" "n3-p5-p7ncn.20")@@@list("jennifer_hsu" "2015/09/07 11:47:04" nil "P143000039-PC" "n3-p5-p7ncn.20") | list("[Electrical] ALL" "194.Propagation Delay" "::0.00 MIL:6500.00 MIL [PROPAGATION_DELAY]" "10430.67 MIL" "" "DRC ERROR CLASS/ALL" "[PinPair] <uTiL>cId5890<uTiL>.39:<uTiL>cId3020<uTiL>.H33 ((7323.11 1795.79) (1347.9 5451.31))" " " list(1347.900000 5451.310000) nil)@@@list("kelly1_pan" "2015/09/04 14:31:23" nil "P143000035-PC" "n3-p5-p7ncn.20")@@@list("jennifer_hsu" "2015/09/07 11:47:05" nil "P143000039-PC" "n3-p5-p7ncn.20") | list("[Electrical] ALL" "184.Propagation Delay" "::0.00 MIL:6500.00 MIL [PROPAGATION_DELAY]" "11022.29 MIL" "" "DRC ERROR CLASS/ALL" "[PinPair] <uTiL>cId5890<uTiL>.42:<uTiL>cId3020<uTiL>.G38 ((7323.11 1736.73) (1367.89 5579.31))" " " list(1367.890000 5579.310000) nil)@@@list("kelly1_pan" "2015/09/04 14:31:09" nil "P143000035-PC" "n3-p5-p7ncn.20")@@@list("jennifer_hsu" "2015/09/07 11:46:55" nil "P143000039-PC" "n3-p5-p7ncn.20") | list("[Electrical] ALL" "183.Propagation Delay" "::0.00 MIL:6500.00 MIL [PROPAGATION_DELAY]" "11024.48 MIL" "" "DRC ERROR CLASS/ALL" "[PinPair] <uTiL>cId5890<uTiL>.41:<uTiL>cId3020<uTiL>.F37 ((7323.11 1756.42) (1378.9 5553.71))" " " list(1378.900000 5553.710000) nil)@@@list("kelly1_pan" "2015/09/04 14:31:09" nil "P143000035-PC" "n3-p5-p7ncn.20")@@@list("jennifer_hsu" "2015/09/07 11:46:54" nil "P143000039-PC" "n3-p5-p7ncn.20") | list("[Electrical] ALL" "178.Propagation Delay" "::0.00 MIL:6500.00 MIL [PROPAGATION_DELAY]" "10564.16 MIL" "" "DRC ERROR CLASS/ALL" "[PinPair] <uTiL>cId5890<uTiL>.45:<uTiL>cId3020<uTiL>.F35 ((7323.11 1677.68) (1378.9 5502.51))" " " list(1378.900000 5502.510000) nil)@@@list("kelly1_pan" "2015/09/04 14:31:03" nil "P143000035-PC" "n3-p5-p7ncn.20")@@@list("jennifer_hsu" "2015/09/07 11:46:49" nil "P143000039-PC" "n3-p5-p7ncn.20") | list("[Electrical] ALL" "179.Propagation Delay" "::0.00 MIL:6500.00 MIL [PROPAGATION_DELAY]" "10561.69 MIL" "" "DRC ERROR CLASS/ALL" "[PinPair] <uTiL>cId5890<uTiL>.44:<uTiL>cId3020<uTiL>.F34 ((7323.11 1697.36) (1378.9 5476.91))" " " list(1378.900000 5476.910000) nil)@@@list("kelly1_pan" "2015/09/04 14:31:04" nil "P143000035-PC" "n3-p5-p7ncn.20")@@@list("jennifer_hsu" "2015/09/07 11:46:50" nil "P143000039-PC" "n3-p5-p7ncn.20") | list("[Electrical] ALL" "180.Propagation Delay" "::0.00 MIL:6500.00 MIL [PROPAGATION_DELAY]" "10611.72 MIL" "" "DRC ERROR CLASS/ALL" "[PinPair] <uTiL>cId5890<uTiL>.47:<uTiL>cId3020<uTiL>.E37 ((7323.11 1638.31) (1409.9 5553.71))" " " list(1409.900000 5553.710000) nil)@@@list("kelly1_pan" "2015/09/04 14:31:05" nil "P143000035-PC" "n3-p5-p7ncn.20")@@@list("jennifer_hsu" "2015/09/07 11:46:50" nil "P143000039-PC" "n3-p5-p7ncn.20") | list("[Electrical] ALL" "181.Propagation Delay" "::0.00 MIL:6500.00 MIL [PROPAGATION_DELAY]" "10614.72 MIL" "" "DRC ERROR CLASS/ALL" "[PinPair] <uTiL>cId5890<uTiL>.48:<uTiL>cId3020<uTiL>.E36 ((7323.11 1618.62) (1409.9 5528.11))" " " list(1409.900000 5528.110000) nil)@@@list("kelly1_pan" "2015/09/04 14:31:07" nil "P143000035-PC" "n3-p5-p7ncn.20")@@@list("jennifer_hsu" "2015/09/07 11:46:52" nil "P143000039-PC" "n3-p5-p7ncn.20") | list("[Electrical] ALL" "189.Propagation Delay" "::0.00 MIL:6900.00 MIL [PROPAGATION_DELAY]" "10692.07 MIL" "" "DRC ERROR CLASS/ALL" "[PinPair] <uTiL>cId5889<uTiL>.39:<uTiL>cId3020<uTiL>.D34 ((7288.11 1245.79) (1435.63 5475.95))" " " list(1435.630000 5475.950000) nil)@@@list("kelly1_pan" "2015/09/04 14:31:16" nil "P143000035-PC" "n3-p5-p7ncn.20")@@@list("jennifer_hsu" "2015/09/07 11:47:00" nil "P143000039-PC" "n3-p5-p7ncn.20") | list("[Package] BOTTOM" "392.Pkg to Pkg Spacing" "0 MIL [PACKAGE_HEIGHT_MIN]" "27.56 MIL" "-27.56 MIL" "DRC ERROR CLASS/PACKAGE_BOTTOM" "[Shape] Package Geometry/Place_Bound_Bottom ((1444.37 6548.7) (1515.63 6675.08))" "[Shape] Package Geometry/Place_Bound_Bottom ((1436.69 6550.87) (1523.31 6672.91))" list(1444.370000 6550.870000) nil)@@@list("kelly1_pan" "2015/09/04 16:12:33" nil "P143000035-PC" "n3-p5-p7ncn.20")@@@list("jennifer_hsu" "2015/09/07 11:50:42" nil "P143000039-PC" "n3-p5-p7ncn.20") | list("[Package] BOTTOM" "381.Pkg to Place Keepin Spacing" "0 MIL [NONE]" "138.64 MIL" "-138.64 MIL" "DRC ERROR CLASS/PACKAGE_BOTTOM" "[Shape] Package Keepin/All ((-897.01 -353.7) (9751.34 6916.7))" "[Shape] Package Geometry/Place_Bound_Bottom ((1365.96 7055.34) (1556.08 7245.46))" list(1461.030000 6916.700000) nil)@@@list("kelly1_pan" "2015/09/04 16:12:22" nil "P143000035-PC" "n3-p5-p7ncn.20")@@@list("jennifer_hsu" "2015/09/07 11:50:32" nil "P143000039-PC" "n3-p5-p7ncn.20") | list("[Package] TOP" "320.Pkg to Place Keepin Spacing" "0 MIL [NONE]" "1032.34 MIL" "-1032.34 MIL" "DRC ERROR CLASS/PACKAGE_TOP" "[Shape] Package Keepin/All ((-897.01 -353.7) (9751.34 6916.7))" "[Shape] Package Geometry/Place_Bound_Top ((1365.96 -603.72) (1556.08 -413.6))" list(1461.030000 618.740000) nil)@@@list("kelly1_pan" "2015/09/04 16:11:11" nil "P143000035-PC" "n3-p5-p7ncn.20")@@@list("jennifer_hsu" "2015/09/07 11:49:26" nil "P143000039-PC" "n3-p5-p7ncn.20") | list("[Electrical] ALL" "192.Diffpair Max Uncoupled Length" "200 MIL [DIFFP_UNCOUPLED_LENGTH]" "277.74 MIL" "-77.74 MIL" "DRC ERROR CLASS/ALL" "[PinPair] <uTiL>cId5889<uTiL>.48:<uTiL>cId3020<uTiL>.B33 ((7288.11 1068.62) (1486.83 5444.95))" "[PinPair] <uTiL>cId5889<uTiL>.47:<uTiL>cId3020<uTiL>.C33 ((7288.11 1088.31) (1461.23 5444.95))" list(1461.230000 5444.950000) nil)@@@list("kelly1_pan" "2015/09/04 14:31:21" nil "P143000035-PC" "n3-p5-p7ncn.20")@@@list("jennifer_hsu" "2015/09/07 11:47:03" nil "P143000039-PC" "n3-p5-p7ncn.20") | list("[Electrical] ALL" "191.Diffpair Max Uncoupled Length" "200 MIL [DIFFP_UNCOUPLED_LENGTH]" "216.77 MIL" "-16.77 MIL" "DRC ERROR CLASS/ALL" "[PinPair] <uTiL>cId5889<uTiL>.41:<uTiL>cId3020<uTiL>.B36 ((7288.11 1206.42) (1484.83 5523.01))" "[PinPair] <uTiL>cId5889<uTiL>.42:<uTiL>cId3020<uTiL>.B34 ((7288.11 1186.73) (1486.07 5493.27))" list(1486.070000 5493.270000) nil)@@@list("kelly1_pan" "2015/09/04 14:31:19" nil "P143000035-PC" "n3-p5-p7ncn.20")@@@list("jennifer_hsu" "2015/09/07 11:47:02" nil "P143000039-PC" "n3-p5-p7ncn.20") | list("[Electrical] ALL" "274.Relative Propagation Delay" "R_M_CHB_ADD:G::::200.00 MIL [RELATIVE_PROPAGATION_DELAY]" "201.08 MIL" "" "DRC ERROR CLASS/ALL" "[PinPair] <uTiL>cId3020<uTiL>.AL5:<uTiL>cId3009<uTiL>.131 ((634.5 4633.35) (1587.6 2177.17))" "[PinPair] <uTiL>cId3010<uTiL>.115:<uTiL>cId3020<uTiL>.AR9 ((1508.87 1854.34) (507.67 4736.13))" list(1508.870000 1854.340000) nil)@@@list("kelly1_pan" "2015/09/04 16:10:06" nil "P143000035-PC" "n3-p5-p7ncn.20")@@@list("jennifer_hsu" "2015/09/07 11:48:29" nil "P143000039-PC" "n3-p5-p7ncn.20") | list("[Package] BOTTOM" "393.Pkg to Pkg Spacing" "0 MIL [PACKAGE_HEIGHT_MIN]" "27.56 MIL" "-27.56 MIL" "DRC ERROR CLASS/PACKAGE_BOTTOM" "[Shape] Package Geometry/Place_Bound_Bottom ((1544.37 6548.7) (1615.63 6675.08))" "[Shape] Package Geometry/Place_Bound_Bottom ((1536.69 6550.87) (1623.31 6672.91))" list(1544.370000 6550.870000) nil)@@@list("kelly1_pan" "2015/09/04 16:12:34" nil "P143000035-PC" "n3-p5-p7ncn.20")@@@list("jennifer_hsu" "2015/09/07 11:50:43" nil "P143000039-PC" "n3-p5-p7ncn.20") | list("[Package] TOP" "334.Pkg to Pkg Spacing" "0 MIL [PACKAGE_HEIGHT_MIN]" "2 MIL" "-2.00 MIL" "DRC ERROR CLASS/PACKAGE_TOP" "[Shape] Package Geometry/Place_Bound_Top ((1419.07 5664.29) (1702.93 6019.49))" "[Shape] Package Geometry/Place_Bound_Top ((1537.5 5759.39) (1562.5 5784.39))" list(1550.000000 5664.290000) nil)@@@list("kelly1_pan" "2015/09/04 16:11:30" nil "P143000035-PC" "n3-p5-p7ncn.20")@@@list("jennifer_hsu" "2015/09/07 11:49:46" nil "P143000039-PC" "n3-p5-p7ncn.20") | list("[Electrical] ALL" "170.Diffpair Max Uncoupled Length" "200 MIL [DIFFP_UNCOUPLED_LENGTH]" "236.78 MIL" "-36.78 MIL" "DRC ERROR CLASS/ALL" "[PinPair] <uTiL>cId3020<uTiL>.C26:<uTiL>cId4010<uTiL>.14 ((1461.23 5258.95) (1572.73 6745.09))" "[PinPair] <uTiL>cId3020<uTiL>.B26:<uTiL>cId4010<uTiL>.15 ((1486.83 5258.95) (1553.05 6745.09))" list(1553.050000 6745.090000) nil)@@@list("kelly1_pan" "2015/09/04 14:30:18" nil "P143000035-PC" "n3-p5-p7ncn.20")@@@list("jennifer_hsu" "2015/09/07 11:46:40" nil "P143000039-PC" "n3-p5-p7ncn.20") | list("[Electrical] ALL" "275.Relative Propagation Delay" "R_M_CHB_ADD:G::::200.00 MIL [RELATIVE_PROPAGATION_DELAY]" "209.74 MIL" "" "DRC ERROR CLASS/ALL" "[PinPair] <uTiL>cId3020<uTiL>.AL5:<uTiL>cId3009<uTiL>.131 ((634.5 4633.35) (1587.6 2177.17))" "[PinPair] <uTiL>cId3010<uTiL>.120:<uTiL>cId3020<uTiL>.AN11 ((1558.08 2177.18) (579.67 4787.33))" list(1558.080000 2177.180000) nil)@@@list("kelly1_pan" "2015/09/04 16:10:07" nil "P143000035-PC" "n3-p5-p7ncn.20")@@@list("jennifer_hsu" "2015/09/07 11:48:30" nil "P143000039-PC" "n3-p5-p7ncn.20") | list("[Package] TOP" "333.Pkg to Pkg Spacing" "0 MIL [PACKAGE_HEIGHT_MIN]" "2 MIL" "-2.00 MIL" "DRC ERROR CLASS/PACKAGE_TOP" "[Shape] Package Geometry/Place_Bound_Top ((1419.07 5664.29) (1702.93 6019.49))" "[Shape] Package Geometry/Place_Bound_Top ((1547.5 5899.39) (1572.5 5924.39))" list(1560.000000 6019.490000) nil)@@@list("kelly1_pan" "2015/09/04 16:11:29" nil "P143000035-PC" "n3-p5-p7ncn.20")@@@list("jennifer_hsu" "2015/09/07 11:49:46" nil "P143000039-PC" "n3-p5-p7ncn.20") | list("[Electrical] ALL" "276.Relative Propagation Delay" "R_M_CHB_ADD:G::::200.00 MIL [RELATIVE_PROPAGATION_DELAY]" "225.37 MIL" "" "DRC ERROR CLASS/ALL" "[PinPair] <uTiL>cId3020<uTiL>.AL5:<uTiL>cId3009<uTiL>.131 ((634.5 4633.35) (1587.6 2177.17))" "[PinPair] <uTiL>cId3010<uTiL>.122:<uTiL>cId3020<uTiL>.AN10 ((1577.77 2177.18) (579.67 4761.73))" list(1577.770000 2177.180000) nil)@@@list("kelly1_pan" "2015/09/04 16:10:08" nil "P143000035-PC" "n3-p5-p7ncn.20")@@@list("jennifer_hsu" "2015/09/07 11:48:31" nil "P143000039-PC" "n3-p5-p7ncn.20") | list("[Electrical] ALL" "186.Diffpair Max Uncoupled Length" "200 MIL [DIFFP_UNCOUPLED_LENGTH]" "223.98 MIL" "-23.98 MIL" "DRC ERROR CLASS/ALL" "[PinPair] <uTiL>cId4010<uTiL>.11:<uTiL>cId3020<uTiL>.E29 ((1631.79 6745.09) (1410.03 5351.95))" "[PinPair] <uTiL>cId4010<uTiL>.12:<uTiL>cId3020<uTiL>.D29 ((1612.1 6745.09) (1435.63 5351.95))" list(1612.100000 6745.090000) nil)@@@list("kelly1_pan" "2015/09/04 14:31:12" nil "P143000035-PC" "n3-p5-p7ncn.20")@@@list("jennifer_hsu" "2015/09/07 11:46:57" nil "P143000039-PC" "n3-p5-p7ncn.20") | list("[Package] BOTTOM" "394.Pkg to Pkg Spacing" "0 MIL [PACKAGE_HEIGHT_MIN]" "27.56 MIL" "-27.56 MIL" "DRC ERROR CLASS/PACKAGE_BOTTOM" "[Shape] Package Geometry/Place_Bound_Bottom ((1644.37 6548.7) (1715.63 6675.08))" "[Shape] Package Geometry/Place_Bound_Bottom ((1636.69 6550.87) (1723.31 6672.91))" list(1644.370000 6550.870000) nil)@@@list("kelly1_pan" "2015/09/04 16:12:35" nil "P143000035-PC" "n3-p5-p7ncn.20")@@@list("jennifer_hsu" "2015/09/07 11:50:44" nil "P143000039-PC" "n3-p5-p7ncn.20") | list("[Electrical] ALL" "188.Diffpair Max Uncoupled Length" "200 MIL [DIFFP_UNCOUPLED_LENGTH]" "211.72 MIL" "-11.72 MIL" "DRC ERROR CLASS/ALL" "[PinPair] <uTiL>cId3020<uTiL>.F28:<uTiL>cId4010<uTiL>.9 ((1384.43 5320.95) (1671.16 6745.09))" "[PinPair] <uTiL>cId3020<uTiL>.E28:<uTiL>cId4010<uTiL>.8 ((1410.03 5320.95) (1690.84 6745.09))" list(1690.840000 6745.090000) nil)@@@list("kelly1_pan" "2015/09/04 14:31:15" nil "P143000035-PC" "n3-p5-p7ncn.20")@@@list("jennifer_hsu" "2015/09/07 11:46:59" nil "P143000039-PC" "n3-p5-p7ncn.20") | list("[Package] BOTTOM" "352.Pkg to Place Keepin Spacing" "0 MIL [NONE]" "0 MIL" "0.00 MIL" "DRC ERROR CLASS/PACKAGE_BOTTOM" "[Shape] Package Keepin/All ((-897.01 -353.7) (9751.34 6916.7))" "[Shape] Package Geometry/Place_Bound_Bottom ((1690.25 594.68) (2135.15 836.59))" list(1701.870000 618.740000) nil)@@@list("kelly1_pan" "2015/09/04 16:11:52" nil "P143000035-PC" "n3-p5-p7ncn.20")@@@list("jennifer_hsu" "2015/09/07 11:50:02" nil "P143000039-PC" "n3-p5-p7ncn.20") | list("[Electrical] ALL" "214.Diffpair Max Uncoupled Length" "200 MIL [DIFFP_UNCOUPLED_LENGTH]" "233.18 MIL" "-33.18 MIL" "DRC ERROR CLASS/ALL" "[PinPair] <uTiL>cId3020<uTiL>.B29:<uTiL>cId4010<uTiL>.5 ((1486.83 5351.95) (1749.9 6745.09))" "[PinPair] <uTiL>cId4010<uTiL>.6:<uTiL>cId3020<uTiL>.A29 ((1730.21 6745.09) (1512.43 5351.95))" list(1730.210000 6745.090000) nil)@@@list("kelly1_pan" "2015/09/04 14:31:44" nil "P143000035-PC" "n3-p5-p7ncn.20")@@@list("jennifer_hsu" "2015/09/07 11:47:26" nil "P143000039-PC" "n3-p5-p7ncn.20") | list("[Package] BOTTOM" "395.Pkg to Pkg Spacing" "0 MIL [PACKAGE_HEIGHT_MIN]" "27.56 MIL" "-27.56 MIL" "DRC ERROR CLASS/PACKAGE_BOTTOM" "[Shape] Package Geometry/Place_Bound_Bottom ((1744.37 6548.7) (1815.63 6675.08))" "[Shape] Package Geometry/Place_Bound_Bottom ((1736.69 6550.87) (1823.31 6672.91))" list(1744.370000 6550.870000) nil)@@@list("kelly1_pan" "2015/09/04 16:12:36" nil "P143000035-PC" "n3-p5-p7ncn.20")@@@list("jennifer_hsu" "2015/09/07 11:50:45" nil "P143000039-PC" "n3-p5-p7ncn.20") | list("[Package] BOTTOM" "1.Pkg to Pkg Spacing" "0 MIL [PACKAGE_HEIGHT_MIN]" "2 MIL" "-2.00 MIL" "DRC ERROR CLASS/PACKAGE_BOTTOM" "[Shape] Package Geometry/Place_Bound_Bottom ((1833.39 5945.79) (1876.61 6027.99))" "[Shape] Package Geometry/Place_Bound_Bottom ((1849.5 5962.39) (1874.5 5987.39))" list(1876.610000 5974.890000) nil)@@@list("kelly1_pan" "2015/09/04 16:12:46" nil "P143000035-PC" "n3-p5-p7ncn.20")@@@list("jennifer_hsu" "2015/09/07 11:58:46" nil "P143000039-PC" "n3-p5-p7ncn.20") | list("[Package] BOTTOM" "383.Pkg to Pkg Spacing" "0 MIL [PACKAGE_HEIGHT_MIN]" "27.56 MIL" "-27.56 MIL" "DRC ERROR CLASS/PACKAGE_BOTTOM" "[Shape] Package Geometry/Place_Bound_Bottom ((1884.37 6573.7) (1955.63 6700.08))" "[Shape] Package Geometry/Place_Bound_Bottom ((1876.69 6575.87) (1963.31 6697.91))" list(1884.370000 6575.870000) nil)@@@list("kelly1_pan" "2015/09/04 16:12:24" nil "P143000035-PC" "n3-p5-p7ncn.20")@@@list("jennifer_hsu" "2015/09/07 11:50:35" nil "P143000039-PC" "n3-p5-p7ncn.20") | list("[Package] TOP" "296.Pkg to Place Keepout Spacing" "0 MIL [NONE]" "110.24 MIL" "-110.24 MIL" "DRC ERROR CLASS/PACKAGE_TOP" "[Shape] Package Keepout/Top ((882.7 6349.8) (2021.4 6969.1))" "[Shape] Package Geometry/Place_Bound_Top ((913.28 6460.64) (1976.28 6787.41))" list(1964.300000 6460.640000) nil)@@@list("kelly1_pan" "2015/09/04 16:10:42" nil "P143000035-PC" "n3-p5-p7ncn.20")@@@list("jennifer_hsu" "2015/09/07 11:49:00" nil "P143000039-PC" "n3-p5-p7ncn.20") | list("[Package] BOTTOM" "371.Pkg to Pkg Spacing" "0 MIL [PACKAGE_HEIGHT_MIN]" "157.48 MIL" "-157.48 MIL" "DRC ERROR CLASS/PACKAGE_BOTTOM" "[Shape] Package Geometry/Place_Bound_Bottom ((1972.5 6244.39) (1997.5 6269.39))" "[Shape] Package Geometry/Place_Bound_Bottom ((1877.4 6114.96) (2232.6 6398.82))" list(1972.500000 6256.890000) nil)@@@list("kelly1_pan" "2015/09/04 16:12:12" nil "P143000035-PC" "n3-p5-p7ncn.20")@@@list("jennifer_hsu" "2015/09/07 11:50:25" nil "P143000039-PC" "n3-p5-p7ncn.20") | list("[Electrical] ALL" "277.Relative Propagation Delay" "R_M_CHB_ADD:G::::200.00 MIL [RELATIVE_PROPAGATION_DELAY]" "222.91 MIL" "" "DRC ERROR CLASS/ALL" "[PinPair] <uTiL>cId3020<uTiL>.AL5:<uTiL>cId3009<uTiL>.131 ((634.5 4633.35) (1587.6 2177.17))" "[PinPair] <uTiL>cId3010<uTiL>.156:<uTiL>cId3020<uTiL>.AF8 ((1991.15 2177.18) (795.67 4710.53))" list(1991.150000 2177.180000) nil)@@@list("kelly1_pan" "2015/09/04 16:10:12" nil "P143000035-PC" "n3-p5-p7ncn.20")@@@list("jennifer_hsu" "2015/09/07 11:48:32" nil "P143000039-PC" "n3-p5-p7ncn.20") | list("[Package] BOTTOM" "372.Pkg to Pkg Spacing" "0 MIL [PACKAGE_HEIGHT_MIN]" "157.48 MIL" "-157.48 MIL" "DRC ERROR CLASS/PACKAGE_BOTTOM" "[Shape] Package Geometry/Place_Bound_Bottom ((2112.5 6249.39) (2137.5 6274.39))" "[Shape] Package Geometry/Place_Bound_Bottom ((1877.4 6114.96) (2232.6 6398.82))" list(2137.500000 6261.890000) nil)@@@list("kelly1_pan" "2015/09/04 16:12:13" nil "P143000035-PC" "n3-p5-p7ncn.20")@@@list("jennifer_hsu" "2015/09/07 11:50:26" nil "P143000039-PC" "n3-p5-p7ncn.20") | list("[Electrical] ALL" "289.Diffpair Max Uncoupled Length" "200 MIL [DIFFP_UNCOUPLED_LENGTH]" "211.96 MIL" "-11.96 MIL" "DRC ERROR CLASS/ALL" "[PinPair] <uTiL>cId3020<uTiL>.AA9:<uTiL>cId3010<uTiL>.179 ((939.67 4736.13) (2217.53 1854.34))" "[PinPair] <uTiL>cId3020<uTiL>.AC9:<uTiL>cId3010<uTiL>.177 ((903.67 4736.13) (2197.85 1854.34))" list(2197.850000 1854.340000) nil)@@@list("kelly1_pan" "2015/09/04 16:10:33" nil "P143000035-PC" "n3-p5-p7ncn.20")@@@list("jennifer_hsu" "2015/09/07 11:48:45" nil "P143000039-PC" "n3-p5-p7ncn.20") | list("[Package] BOTTOM" "351.Pkg to Place Keepin Spacing" "0 MIL [NONE]" "0 MIL" "0.00 MIL" "DRC ERROR CLASS/PACKAGE_BOTTOM" "[Shape] Package Keepin/All ((-897.01 -353.7) (9751.34 6916.7))" "[Shape] Package Geometry/Place_Bound_Bottom ((2470.27 452.58) (3809.25 862.55))" list(2488.820000 452.580000) nil)@@@list("kelly1_pan" "2015/09/04 16:11:51" nil "P143000035-PC" "n3-p5-p7ncn.20")@@@list("jennifer_hsu" "2015/09/07 11:50:01" nil "P143000039-PC" "n3-p5-p7ncn.20") | list("[Package] BOTTOM" "353.Pkg to Place Keepout Spacing" "0 MIL [NONE]" "43.31 MIL" "-43.31 MIL" "DRC ERROR CLASS/PACKAGE_BOTTOM" "[Shape] Package Geometry/Place_Bound_Bottom ((2402.82 4022.21) (2682.84 4302.23))" "[Shape] Package Keepout/Bottom ((2507.95 4295.31) (2862.28 4649.64))" list(2507.950000 4297.820000) nil)@@@list("kelly1_pan" "2015/09/04 16:11:53" nil "P143000035-PC" "n3-p5-p7ncn.20")@@@list("jennifer_hsu" "2015/09/07 11:50:03" nil "P143000039-PC" "n3-p5-p7ncn.20") | list("[Package] TOP" "304.Pkg to Place Keepin Spacing" "0 MIL [NONE]" "0 MIL" "0.00 MIL" "DRC ERROR CLASS/PACKAGE_TOP" "[Shape] Package Keepin/All ((-897.01 -353.7) (9751.34 6916.7))" "[Shape] Package Geometry/Place_Bound_Top ((2535.86 6710.49) (3111.06 6946.99))" list(2535.860000 6916.700000) nil)@@@list("kelly1_pan" "2015/09/04 16:10:50" nil "P143000035-PC" "n3-p5-p7ncn.20")@@@list("jennifer_hsu" "2015/09/07 11:49:06" nil "P143000039-PC" "n3-p5-p7ncn.20") | list("[Package] BOTTOM" "396.Pkg to Pkg Spacing" "0 MIL [PACKAGE_HEIGHT_MIN]" "27.56 MIL" "-27.56 MIL" "DRC ERROR CLASS/PACKAGE_BOTTOM" "[Shape] Package Geometry/Place_Bound_Bottom ((2559.37 6638.7) (2630.63 6765.08))" "[Shape] Package Geometry/Place_Bound_Bottom ((2551.69 6640.87) (2638.31 6762.91))" list(2559.370000 6640.870000) nil)@@@list("kelly1_pan" "2015/09/04 16:12:37" nil "P143000035-PC" "n3-p5-p7ncn.20")@@@list("jennifer_hsu" "2015/09/07 11:50:46" nil "P143000039-PC" "n3-p5-p7ncn.20") | list("[Package] TOP" "346.Pkg to Pkg Spacing" "0 MIL [PACKAGE_HEIGHT_MIN]" "2 MIL" "-2.00 MIL" "DRC ERROR CLASS/PACKAGE_TOP" "[Shape] Package Geometry/Place_Bound_Top ((2573.39 6228.9) (2616.61 6311.1))" "[Shape] Package Geometry/Place_Bound_Top ((2577.5 6267.5) (2602.5 6292.5))" list(2577.500000 6267.500000) nil)@@@list("kelly1_pan" "2015/09/04 16:11:43" nil "P143000035-PC" "n3-p5-p7ncn.20")@@@list("jennifer_hsu" "2015/09/07 11:49:57" nil "P143000039-PC" "n3-p5-p7ncn.20") | list("[Package] BOTTOM" "397.Pkg to Pkg Spacing" "0 MIL [PACKAGE_HEIGHT_MIN]" "27.56 MIL" "-27.56 MIL" "DRC ERROR CLASS/PACKAGE_BOTTOM" "[Shape] Package Geometry/Place_Bound_Bottom ((2654.37 6638.7) (2725.63 6765.08))" "[Shape] Package Geometry/Place_Bound_Bottom ((2646.69 6640.87) (2733.31 6762.91))" list(2654.370000 6640.870000) nil)@@@list("kelly1_pan" "2015/09/04 16:12:39" nil "P143000035-PC" "n3-p5-p7ncn.20")@@@list("jennifer_hsu" "2015/09/07 11:50:47" nil "P143000039-PC" "n3-p5-p7ncn.20") | list("[Package] TOP" "345.Pkg to Pkg Spacing" "0 MIL [PACKAGE_HEIGHT_MIN]" "2 MIL" "-2.00 MIL" "DRC ERROR CLASS/PACKAGE_TOP" "[Shape] Package Geometry/Place_Bound_Top ((2676.0 6526.0) (2734.0 6554.0))" "[Shape] Package Geometry/Place_Bound_Top ((2677.5 6542.5) (2702.5 6567.5))" list(2677.500000 6554.000000) nil)@@@list("kelly1_pan" "2015/09/04 16:11:42" nil "P143000035-PC" "n3-p5-p7ncn.20")@@@list("jennifer_hsu" "2015/09/07 11:49:56" nil "P143000039-PC" "n3-p5-p7ncn.20") | list("[Electrical] ALL" "176.Propagation Delay" "::0 mil:8500 mil [PROPAGATION_DELAY]" "8754.62 MIL" "" "DRC ERROR CLASS/ALL" "[PinPair] <uTiL>cId6167<uTiL>.45:<uTiL>cId2999<uTiL>.BC12 ((8603.11 3750.79) (2807.16 4752.0))" " " list(2807.160000 4752.000000) nil)@@@list("kelly1_pan" "2015/09/04 14:30:27" nil "P143000035-PC" "n3-p5-p7ncn.20")@@@list("jennifer_hsu" "2015/09/07 11:46:46" nil "P143000039-PC" "n3-p5-p7ncn.20") | list("[Electrical] ALL" "171.Diffpair Phase Tolerance" "5 mil [DIFFP_PHASE_TOL]" "19.37 MIL" "" "DRC ERROR CLASS/ALL" "[PinPair] <uTiL>cId6540<uTiL>.20:<uTiL>cId71<uTiL>.A16 ((2880.07 6737.32) (5354.26 1782.65))" "[PinPair] <uTiL>cId6540<uTiL>.19:<uTiL>cId71<uTiL>.B16 ((2860.39 6737.32) (5374.26 1782.65))" list(2860.390000 6737.320000) nil)@@@list("kelly1_pan" "2015/09/04 14:30:20" nil "P143000035-PC" "n3-p5-p7ncn.20")@@@list("jennifer_hsu" "2015/09/07 11:46:42" nil "P143000039-PC" "n3-p5-p7ncn.20") | list("[Package] BOTTOM" "354.Pkg to Pkg Spacing" "0 MIL [PACKAGE_HEIGHT_MIN]" "214.57 MIL" "-214.57 MIL" "DRC ERROR CLASS/PACKAGE_BOTTOM" "[Shape] Package Geometry/Place_Bound_Bottom ((74.61 1807.82) (3169.49 2848.62))" "[Shape] Package Geometry/Place_Bound_Bottom ((74.61 2280.27) (3169.49 3321.07))" list(3099.810000 2569.200000) nil)@@@list("kelly1_pan" "2015/09/04 16:11:55" nil "P143000035-PC" "n3-p5-p7ncn.20")@@@list("jennifer_hsu" "2015/09/07 11:50:04" nil "P143000039-PC" "n3-p5-p7ncn.20") | list("[Package] TOP" "328.Pkg to Pkg Spacing" "0 MIL [PACKAGE_HEIGHT_MIN]" "2 MIL" "-2.00 MIL" "DRC ERROR CLASS/PACKAGE_TOP" "[Shape] Package Geometry/Place_Bound_Top ((3433.39 2150.79) (3476.61 2232.99))" "[Shape] Package Geometry/Place_Bound_Top ((3437.5 2169.39) (3462.5 2194.39))" list(3433.390000 2181.890000) nil)@@@list("kelly1_pan" "2015/09/04 16:11:22" nil "P143000035-PC" "n3-p5-p7ncn.20")@@@list("jennifer_hsu" "2015/09/07 11:49:42" nil "P143000039-PC" "n3-p5-p7ncn.20") | list("[Package] TOP" "329.Pkg to Pkg Spacing" "0 MIL [PACKAGE_HEIGHT_MIN]" "2 MIL" "-2.00 MIL" "DRC ERROR CLASS/PACKAGE_TOP" "[Shape] Package Geometry/Place_Bound_Top ((3433.39 2150.79) (3476.61 2232.99))" "[Shape] Package Geometry/Place_Bound_Top ((3462.5 2149.39) (3487.5 2174.39))" list(3476.610000 2174.390000) nil)@@@list("kelly1_pan" "2015/09/04 16:11:23" nil "P143000035-PC" "n3-p5-p7ncn.20")@@@list("jennifer_hsu" "2015/09/07 11:49:43" nil "P143000039-PC" "n3-p5-p7ncn.20") | list("[Package] TOP" "331.Pkg to Pkg Spacing" "0 MIL [PACKAGE_HEIGHT_MIN]" "2 MIL" "-2.00 MIL" "DRC ERROR CLASS/PACKAGE_TOP" "[Shape] Package Geometry/Place_Bound_Top ((3649.39 2269.79) (3692.61 2351.99))" "[Shape] Package Geometry/Place_Bound_Top ((3658.5 2308.39) (3683.5 2333.39))" list(3649.390000 2320.890000) nil)@@@list("kelly1_pan" "2015/09/04 16:11:27" nil "P143000035-PC" "n3-p5-p7ncn.20")@@@list("jennifer_hsu" "2015/09/07 11:49:44" nil "P143000039-PC" "n3-p5-p7ncn.20") | list("[Package] TOP" "330.Pkg to Pkg Spacing" "0 MIL [PACKAGE_HEIGHT_MIN]" "2 MIL" "-2.00 MIL" "DRC ERROR CLASS/PACKAGE_TOP" "[Shape] Package Geometry/Place_Bound_Top ((3649.39 2269.79) (3692.61 2351.99))" "[Shape] Package Geometry/Place_Bound_Top ((3683.5 2323.39) (3708.5 2348.39))" list(3692.610000 2323.390000) nil)@@@list("kelly1_pan" "2015/09/04 16:11:25" nil "P143000035-PC" "n3-p5-p7ncn.20")@@@list("jennifer_hsu" "2015/09/07 11:49:44" nil "P143000039-PC" "n3-p5-p7ncn.20") | list("[Package] TOP" "308.Pkg to Place Keepin Spacing" "0 MIL [NONE]" "0 MIL" "0.00 MIL" "DRC ERROR CLASS/PACKAGE_TOP" "[Shape] Package Keepin/All ((-897.01 -353.7) (9751.34 6916.7))" "[Shape] Package Geometry/Place_Bound_Top ((4249.82 6641.71) (4584.82 6956.71))" list(4249.820000 6916.700000) nil)@@@list("kelly1_pan" "2015/09/04 16:10:54" nil "P143000035-PC" "n3-p5-p7ncn.20")@@@list("jennifer_hsu" "2015/09/07 11:49:17" nil "P143000039-PC" "n3-p5-p7ncn.20") | list("[Package] TOP" "332.Pkg to Pkg Spacing" "0 MIL [PACKAGE_HEIGHT_MIN]" "2 MIL" "-2.00 MIL" "DRC ERROR CLASS/PACKAGE_TOP" "[Shape] Package Geometry/Place_Bound_Top ((4228.9 1890.28) (4311.1 1933.5))" "[Shape] Package Geometry/Place_Bound_Top ((4251.5 1896.5) (4276.5 1921.5))" list(4264.000000 1890.280000) nil)@@@list("kelly1_pan" "2015/09/04 16:11:28" nil "P143000035-PC" "n3-p5-p7ncn.20")@@@list("jennifer_hsu" "2015/09/07 11:49:45" nil "P143000039-PC" "n3-p5-p7ncn.20") | list("[Package] BOTTOM" "362.Pkg to Place Keepin Spacing" "0 MIL [NONE]" "0 MIL" "0.00 MIL" "DRC ERROR CLASS/PACKAGE_BOTTOM" "[Shape] Package Keepin/All ((-897.01 -353.7) (9751.34 6916.7))" "[Shape] Package Geometry/Place_Bound_Bottom ((4259.82 6641.71) (4574.82 6956.71))" list(4312.430000 6916.700000) nil)@@@list("kelly1_pan" "2015/09/04 16:12:03" nil "P143000035-PC" "n3-p5-p7ncn.20")@@@list("jennifer_hsu" "2015/09/07 11:50:16" nil "P143000039-PC" "n3-p5-p7ncn.20") | list("[Package] BOTTOM" "401.Pkg to Pkg Spacing" "0 MIL [PACKAGE_HEIGHT_MIN]" "2 MIL" "-2.00 MIL" "DRC ERROR CLASS/PACKAGE_BOTTOM" "[Shape] Package Geometry/Place_Bound_Bottom ((4828.9 2218.39) (4911.1 2261.61))" "[Shape] Package Geometry/Place_Bound_Bottom ((4867.5 2227.5) (4892.5 2252.5))" list(4880.000000 2218.390000) nil)@@@list("kelly1_pan" "2015/09/04 16:12:43" nil "P143000035-PC" "n3-p5-p7ncn.20")@@@list("jennifer_hsu" "2015/09/07 11:50:53" nil "P143000039-PC" "n3-p5-p7ncn.20") | list("[Electrical] ALL" "198.Propagation Delay" "::2500.00 MIL:5000.00 MIL [PROPAGATION_DELAY]" "7589.42 MIL" "" "DRC ERROR CLASS/ALL" "[PinPair] <uTiL>cId4003<uTiL>.40:<uTiL>cId71<uTiL>.A14 ((-557.0 2805.1) (5354.26 1831.15))" " " list(5354.260000 1831.150000) nil)@@@list("kelly1_pan" "2015/09/04 14:31:28" nil "P143000035-PC" "n3-p5-p7ncn.20")@@@list("jennifer_hsu" "2015/09/07 11:47:09" nil "P143000039-PC" "n3-p5-p7ncn.20") | list("[Electrical] ALL" "173.Propagation Delay" "::3000 mil:9000 mil [PROPAGATION_DELAY]" "9397.41 MIL" "" "DRC ERROR CLASS/ALL" "[PinPair] <uTiL>cId6540<uTiL>.20:<uTiL>cId71<uTiL>.A16 ((2880.07 6737.32) (5354.26 1782.65))" " " list(5354.260000 1782.650000) nil)@@@list("kelly1_pan" "2015/09/04 14:30:23" nil "P143000035-PC" "n3-p5-p7ncn.20")@@@list("jennifer_hsu" "2015/09/07 11:46:44" nil "P143000039-PC" "n3-p5-p7ncn.20") | list("[Electrical] ALL" "204.Diffpair Max Uncoupled Length" "200 MIL [DIFFP_UNCOUPLED_LENGTH]" "227.28 MIL" "-27.28 MIL" "DRC ERROR CLASS/ALL" "[PinPair] <uTiL>cId71<uTiL>.B22:<uTiL>cId5095<uTiL>.T22 ((5369.45 1667.15) (8535.67 753.9))" "[PinPair] <uTiL>cId71<uTiL>.A23:<uTiL>cId5095<uTiL>.T23 ((5354.26 1652.15) (8535.67 735.79))" list(5354.260000 1652.150000) nil)@@@list("kelly1_pan" "2015/09/04 14:31:34" nil "P143000035-PC" "n3-p5-p7ncn.20")@@@list("jennifer_hsu" "2015/09/07 11:47:16" nil "P143000039-PC" "n3-p5-p7ncn.20") | list("[Electrical] ALL" "197.Propagation Delay" "::2500.00 MIL:5000.00 MIL [PROPAGATION_DELAY]" "7589.23 MIL" "" "DRC ERROR CLASS/ALL" "[PinPair] <uTiL>cId4003<uTiL>.39:<uTiL>cId71<uTiL>.B13 ((-557.0 2785.41) (5369.45 1846.15))" " " list(5369.450000 1846.150000) nil)@@@list("kelly1_pan" "2015/09/04 14:31:26" nil "P143000035-PC" "n3-p5-p7ncn.20")@@@list("jennifer_hsu" "2015/09/07 11:47:08" nil "P143000039-PC" "n3-p5-p7ncn.20") | list("[Electrical] ALL" "247.Propagation Delay" "::2500 mil:5000 mil [PROPAGATION_DELAY]" "7097.41 MIL" "" "DRC ERROR CLASS/ALL" "[PinPair] <uTiL>cId4003<uTiL>.8:<uTiL>cId71<uTiL>.B15 ((-557.0 2175.17) (5370.71 1806.9))" " " list(5370.710000 1806.900000) nil)@@@list("kelly1_pan" "2015/09/04 14:32:41" nil "P143000035-PC" "n3-p5-p7ncn.20")@@@list("jennifer_hsu" "2015/09/07 11:48:00" nil "P143000039-PC" "n3-p5-p7ncn.20") | list("[Electrical] ALL" "172.Propagation Delay" "::300 mil:9000 mil [PROPAGATION_DELAY]" "9416.77 MIL" "" "DRC ERROR CLASS/ALL" "[PinPair] <uTiL>cId6540<uTiL>.19:<uTiL>cId71<uTiL>.B16 ((2860.39 6737.32) (5374.26 1782.65))" " " list(5374.260000 1782.650000) nil)@@@list("kelly1_pan" "2015/09/04 14:30:21" nil "P143000035-PC" "n3-p5-p7ncn.20")@@@list("jennifer_hsu" "2015/09/07 11:46:43" nil "P143000039-PC" "n3-p5-p7ncn.20") | list("[Electrical] ALL" "202.Diffpair Max Uncoupled Length" "200 MIL [DIFFP_UNCOUPLED_LENGTH]" "230.44 MIL" "-30.44 MIL" "DRC ERROR CLASS/ALL" "[PinPair] <uTiL>cId71<uTiL>.A35:<uTiL>cId3999<uTiL>.13 ((5354.26 1424.65) (1331.7 1549.22))" "[PinPair] <uTiL>cId71<uTiL>.B35:<uTiL>cId3999<uTiL>.11 ((5374.26 1424.65) (1331.7 1568.91))" list(5374.260000 1424.650000) nil)@@@list("kelly1_pan" "2015/09/04 14:31:32" nil "P143000035-PC" "n3-p5-p7ncn.20")@@@list("jennifer_hsu" "2015/09/07 11:47:13" nil "P143000039-PC" "n3-p5-p7ncn.20") | list("[Electrical] ALL" "234.Diffpair Max Uncoupled Length" "200 MIL [DIFFP_UNCOUPLED_LENGTH]" "223.74 MIL" "-23.74 MIL" "DRC ERROR CLASS/ALL" "[PinPair] <uTiL>cId71<uTiL>.B8:<uTiL>cId4004<uTiL>.6 ((5369.45 1937.65) (9299.22 2543.31))" "[PinPair] <uTiL>cId71<uTiL>.C8:<uTiL>cId4004<uTiL>.5 ((5389.1 1941.44) (9299.22 2622.05))" list(5389.100000 1941.440000) nil)@@@list("kelly1_pan" "2015/09/04 14:32:22" nil "P143000035-PC" "n3-p5-p7ncn.20")@@@list("jennifer_hsu" "2015/09/07 11:47:47" nil "P143000039-PC" "n3-p5-p7ncn.20") | list("[Electrical] ALL" "203.Diffpair Max Uncoupled Length" "200 MIL [DIFFP_UNCOUPLED_LENGTH]" "221.71 MIL" "-21.71 MIL" "DRC ERROR CLASS/ALL" "[PinPair] <uTiL>cId71<uTiL>.D22:<uTiL>cId5095<uTiL>.Y22 ((5409.1 1671.94) (8463.23 753.9))" "[PinPair] <uTiL>cId71<uTiL>.C22:<uTiL>cId5095<uTiL>.Y23 ((5389.1 1670.94) (8463.23 735.79))" list(5389.100000 1670.940000) nil)@@@list("kelly1_pan" "2015/09/04 14:31:33" nil "P143000035-PC" "n3-p5-p7ncn.20")@@@list("jennifer_hsu" "2015/09/07 11:47:14" nil "P143000039-PC" "n3-p5-p7ncn.20") | list("[Electrical] ALL" "248.Propagation Delay" "::2500 mil:5000 mil [PROPAGATION_DELAY]" "7100.23 MIL" "" "DRC ERROR CLASS/ALL" "[PinPair] <uTiL>cId4003<uTiL>.9:<uTiL>cId71<uTiL>.C15 ((-557.0 2194.86) (5390.71 1806.9))" " " list(5390.710000 1806.900000) nil)@@@list("kelly1_pan" "2015/09/04 14:32:43" nil "P143000035-PC" "n3-p5-p7ncn.20")@@@list("jennifer_hsu" "2015/09/07 11:48:01" nil "P143000039-PC" "n3-p5-p7ncn.20") | list("[Electrical] ALL" "206.Diffpair Max Uncoupled Length" "200 MIL [DIFFP_UNCOUPLED_LENGTH]" "215.7 MIL" "-15.70 MIL" "DRC ERROR CLASS/ALL" "[PinPair] <uTiL>cId71<uTiL>.B23:<uTiL>cId5095<uTiL>.M23 ((5377.06 1648.13) (8608.11 735.79))" "[PinPair] <uTiL>cId71<uTiL>.C23:<uTiL>cId5095<uTiL>.M22 ((5397.06 1648.13) (8608.11 753.9))" list(5397.060000 1648.130000) nil)@@@list("kelly1_pan" "2015/09/04 14:31:36" nil "P143000035-PC" "n3-p5-p7ncn.20")@@@list("jennifer_hsu" "2015/09/07 11:47:18" nil "P143000039-PC" "n3-p5-p7ncn.20") | list("[Electrical] ALL" "199.Diffpair Max Uncoupled Length" "200 MIL [DIFFP_UNCOUPLED_LENGTH]" "234.79 MIL" "-34.79 MIL" "DRC ERROR CLASS/ALL" "[PinPair] <uTiL>cId71<uTiL>.E37:<uTiL>cId4743<uTiL>.41 ((5424.19 1372.74) (947.83 1273.61))" "[PinPair] <uTiL>cId71<uTiL>.D39:<uTiL>cId4743<uTiL>.43 ((5416.22 1344.19) (947.83 1253.93))" list(5416.220000 1344.190000) nil)@@@list("kelly1_pan" "2015/09/04 14:31:29" nil "P143000035-PC" "n3-p5-p7ncn.20")@@@list("jennifer_hsu" "2015/09/07 11:47:10" nil "P143000039-PC" "n3-p5-p7ncn.20") | list("[Electrical] ALL" "228.Diffpair Max Uncoupled Length" "200 MIL [DIFFP_UNCOUPLED_LENGTH]" "335.9 MIL" "-135.90 MIL" "DRC ERROR CLASS/ALL" "[PinPair] <uTiL>cId71<uTiL>.H13:<uTiL>cId4005<uTiL>.6 ((5494.13 1848.16) (9299.22 1464.57))" "[PinPair] <uTiL>cId71<uTiL>.G13:<uTiL>cId4005<uTiL>.5 ((5464.13 1850.16) (9299.22 1543.31))" list(5464.130000 1850.160000) nil)@@@list("kelly1_pan" "2015/09/04 14:32:00" nil "P143000035-PC" "n3-p5-p7ncn.20")@@@list("jennifer_hsu" "2015/09/07 11:47:41" nil "P143000039-PC" "n3-p5-p7ncn.20") | list("[Electrical] ALL" "245.Propagation Delay" "::2500 mil:5000 mil [PROPAGATION_DELAY]" "7275.12 MIL" "" "DRC ERROR CLASS/ALL" "[PinPair] <uTiL>cId4003<uTiL>.5:<uTiL>cId71<uTiL>.K15 ((-557.0 2116.12) (5522.13 1812.16))" " " list(5522.130000 1812.160000) nil)@@@list("kelly1_pan" "2015/09/04 14:32:39" nil "P143000035-PC" "n3-p5-p7ncn.20")@@@list("jennifer_hsu" "2015/09/07 11:47:58" nil "P143000039-PC" "n3-p5-p7ncn.20") | list("[Electrical] ALL" "246.Propagation Delay" "::2500 mil:5000 mil [PROPAGATION_DELAY]" "7274.14 MIL" "" "DRC ERROR CLASS/ALL" "[PinPair] <uTiL>cId4003<uTiL>.6:<uTiL>cId71<uTiL>.K13 ((-557.0 2135.8) (5524.13 1848.16))" " " list(5524.130000 1848.160000) nil)@@@list("kelly1_pan" "2015/09/04 14:32:40" nil "P143000035-PC" "n3-p5-p7ncn.20")@@@list("jennifer_hsu" "2015/09/07 11:47:59" nil "P143000039-PC" "n3-p5-p7ncn.20") | list("[Package] TOP" "306.Pkg to Place Keepin Spacing" "0 MIL [NONE]" "0 MIL" "0.00 MIL" "DRC ERROR CLASS/PACKAGE_TOP" "[Shape] Package Keepin/All ((-897.01 -353.7) (9751.34 6916.7))" "[Shape] Package Geometry/Place_Bound_Top ((5495.83 5295.2) (5649.62 5626.06))" list(5637.990000 5590.110000) nil)@@@list("kelly1_pan" "2015/09/04 16:10:52" nil "P143000035-PC" "n3-p5-p7ncn.20")@@@list("jennifer_hsu" "2015/09/07 11:49:07" nil "P143000039-PC" "n3-p5-p7ncn.20") | list("[Electrical] ALL" "212.Diffpair Max Uncoupled Length" "200 MIL [DIFFP_UNCOUPLED_LENGTH]" "243.41 MIL" "-43.41 MIL" "DRC ERROR CLASS/ALL" "[PinPair] <uTiL>cId71<uTiL>.AA1:<uTiL>cId4010<uTiL>.33 ((5731.76 2077.63) (1198.72 6745.09))" "[PinPair] <uTiL>cId71<uTiL>.AA2:<uTiL>cId4010<uTiL>.32 ((5731.76 2057.63) (1218.4 6745.09))" list(5731.760000 2057.630000) nil)@@@list("kelly1_pan" "2015/09/04 14:31:42" nil "P143000035-PC" "n3-p5-p7ncn.20")@@@list("jennifer_hsu" "2015/09/07 11:47:24" nil "P143000039-PC" "n3-p5-p7ncn.20") | list("[Electrical] ALL" "236.Diffpair Max Uncoupled Length" "200 MIL [DIFFP_UNCOUPLED_LENGTH]" "238.71 MIL" "-38.71 MIL" "DRC ERROR CLASS/ALL" "[PinPair] <uTiL>cId71<uTiL>.AD5:<uTiL>cId4004<uTiL>.2 ((5806.27 2003.76) (9358.27 2425.2))" "[PinPair] <uTiL>cId71<uTiL>.AD7:<uTiL>cId4004<uTiL>.3 ((5806.27 1973.76) (9358.27 2503.94))" list(5806.270000 1973.760000) nil)@@@list("kelly1_pan" "2015/09/04 14:32:25" nil "P143000035-PC" "n3-p5-p7ncn.20")@@@list("jennifer_hsu" "2015/09/07 11:47:49" nil "P143000039-PC" "n3-p5-p7ncn.20") | list("[Electrical] ALL" "285.Propagation Delay" "::0.00 MIL:5000.00 MIL [PROPAGATION_DELAY]" "8121.93 MIL" "" "DRC ERROR CLASS/ALL" "[PinPair] <uTiL>cId4003<uTiL>.37:<uTiL>cId71<uTiL>.AG8 ((-557.0 2746.04) (5849.77 1943.76))" " " list(5849.770000 1943.760000) nil)@@@list("kelly1_pan" "2015/09/04 16:10:27" nil "P143000035-PC" "n3-p5-p7ncn.20")@@@list("jennifer_hsu" "2015/09/07 11:48:41" nil "P143000039-PC" "n3-p5-p7ncn.20") | list("[Electrical] ALL" "284.Propagation Delay" "::0.00 MIL:5000.00 MIL [PROPAGATION_DELAY]" "8121.56 MIL" "" "DRC ERROR CLASS/ALL" "[PinPair] <uTiL>cId4003<uTiL>.36:<uTiL>cId71<uTiL>.AG10 ((-557.0 2726.36) (5849.77 1913.76))" " " list(5849.770000 1913.760000) nil)@@@list("kelly1_pan" "2015/09/04 16:10:25" nil "P143000035-PC" "n3-p5-p7ncn.20")@@@list("jennifer_hsu" "2015/09/07 11:48:40" nil "P143000039-PC" "n3-p5-p7ncn.20") | list("[Package] BOTTOM" "357.Pkg to Pkg Spacing" "0 MIL [PACKAGE_HEIGHT_MIN]" "21.65 MIL" "-21.65 MIL" "DRC ERROR CLASS/PACKAGE_BOTTOM" "[Shape] Package Geometry/Place_Bound_Bottom ((6354.49 5843.91) (6402.51 5923.29))" "[Shape] Package Geometry/Place_Bound_Bottom ((6314.69 5844.21) (6362.71 5923.59))" list(6354.490000 5923.290000) nil)@@@list("kelly1_pan" "2015/09/04 16:11:58" nil "P143000035-PC" "n3-p5-p7ncn.20")@@@list("jennifer_hsu" "2015/09/07 11:50:11" nil "P143000039-PC" "n3-p5-p7ncn.20") | list("[Package] BOTTOM" "356.Pkg to Place Keepin Spacing" "0 MIL [NONE]" "0 MIL" "0.00 MIL" "DRC ERROR CLASS/PACKAGE_BOTTOM" "[Shape] Package Keepin/All ((-897.01 -353.7) (9751.34 6916.7))" "[Shape] Package Geometry/Place_Bound_Bottom ((6492.14 6145.34) (6692.92 6319.24))" list(6492.140000 6169.920000) nil)@@@list("kelly1_pan" "2015/09/04 16:11:57" nil "P143000035-PC" "n3-p5-p7ncn.20")@@@list("jennifer_hsu" "2015/09/07 11:50:06" nil "P143000039-PC" "n3-p5-p7ncn.20") | list("[Package] TOP" "307.Pkg to Place Keepin Spacing" "0 MIL [NONE]" "0 MIL" "0.00 MIL" "DRC ERROR CLASS/PACKAGE_TOP" "[Shape] Package Keepin/All ((-897.01 -353.7) (9751.34 6916.7))" "[Shape] Package Geometry/Place_Bound_Top ((6175.18 5787.42) (6541.34 6035.63))" list(6515.940000 6011.180000) nil)@@@list("kelly1_pan" "2015/09/04 16:10:53" nil "P143000035-PC" "n3-p5-p7ncn.20")@@@list("jennifer_hsu" "2015/09/07 11:49:08" nil "P143000039-PC" "n3-p5-p7ncn.20") | list("[Package] BOTTOM" "398.Pkg to Pkg Spacing" "0 MIL [PACKAGE_HEIGHT_MIN]" "82.68 MIL" "-82.68 MIL" "DRC ERROR CLASS/PACKAGE_BOTTOM" "[Shape] Package Geometry/Place_Bound_Bottom ((6826.5 2790.5) (6851.5 2815.5))" "[Shape] Package Geometry/Place_Bound_Bottom ((6484.49 2669.84) (6845.51 2863.94))" list(6826.500000 2790.500000) nil)@@@list("kelly1_pan" "2015/09/04 16:12:40" nil "P143000035-PC" "n3-p5-p7ncn.20")@@@list("jennifer_hsu" "2015/09/07 11:50:49" nil "P143000039-PC" "n3-p5-p7ncn.20") | list("[Electrical] ALL" "182.Diffpair Max Uncoupled Length" "200 MIL [DIFFP_UNCOUPLED_LENGTH]" "200.39 MIL" "-0.39 MIL" "DRC ERROR CLASS/ALL" "[PinPair] <uTiL>cId5890<uTiL>.41:<uTiL>cId3020<uTiL>.F37 ((7323.11 1756.42) (1378.9 5553.71))" "[PinPair] <uTiL>cId5890<uTiL>.42:<uTiL>cId3020<uTiL>.G38 ((7323.11 1736.73) (1367.89 5579.31))" list(7323.110000 1736.730000) nil)@@@list("kelly1_pan" "2015/09/04 14:31:08" nil "P143000035-PC" "n3-p5-p7ncn.20")@@@list("jennifer_hsu" "2015/09/07 11:46:53" nil "P143000039-PC" "n3-p5-p7ncn.20") | list("[Package] TOP" "316.Pkg to Place Keepin Spacing" "0 MIL [NONE]" "138.64 MIL" "-138.64 MIL" "DRC ERROR CLASS/PACKAGE_TOP" "[Shape] Package Keepin/All ((-897.01 -353.7) (9751.34 6916.7))" "[Shape] Package Geometry/Place_Bound_Top ((7352.57 7055.34) (7542.69 7245.46))" list(7447.620000 6916.700000) nil)@@@list("kelly1_pan" "2015/09/04 16:11:05" nil "P143000035-PC" "n3-p5-p7ncn.20")@@@list("jennifer_hsu" "2015/09/07 11:49:23" nil "P143000039-PC" "n3-p5-p7ncn.20") | list("[Electrical] ALL" "177.Propagation Delay" "::0.00 MIL:6900.00 MIL [PROPAGATION_DELAY]" "10712.71 MIL" "" "DRC ERROR CLASS/ALL" "[PinPair] <uTiL>cId3020<uTiL>.B27:<uTiL>cId5889<uTiL>.29 ((1486.83 5289.95) (7449.53 1308.78))" " " list(7449.530000 1308.780000) nil)@@@list("kelly1_pan" "2015/09/04 14:30:28" nil "P143000035-PC" "n3-p5-p7ncn.20")@@@list("jennifer_hsu" "2015/09/07 11:46:47" nil "P143000039-PC" "n3-p5-p7ncn.20") | list("[Package] BOTTOM" "378.Pkg to Place Keepin Spacing" "0 MIL [NONE]" "438.02 MIL" "-438.02 MIL" "DRC ERROR CLASS/PACKAGE_BOTTOM" "[Shape] Package Keepin/All ((-897.01 -353.7) (9751.34 6916.7))" "[Shape] Package Geometry/Place_Bound_Bottom ((7352.57 -603.72) (7542.69 -413.6))" list(7461.260000 24.250000) nil)@@@list("kelly1_pan" "2015/09/04 16:12:19" nil "P143000035-PC" "n3-p5-p7ncn.20")@@@list("jennifer_hsu" "2015/09/07 11:50:30" nil "P143000039-PC" "n3-p5-p7ncn.20") | list("[Package] BOTTOM" "377.Pkg to Place Keepin Spacing" "0 MIL [NONE]" "1046.68 MIL" "-1046.68 MIL" "DRC ERROR CLASS/PACKAGE_BOTTOM" "[Shape] Package Keepin/All ((-897.01 -353.7) (9751.34 6916.7))" "[Shape] Package Geometry/Place_Bound_Bottom ((8726.59 7055.34) (8916.71 7245.46))" list(7704.090000 6916.700000) nil)@@@list("kelly1_pan" "2015/09/04 16:12:18" nil "P143000035-PC" "n3-p5-p7ncn.20")@@@list("jennifer_hsu" "2015/09/07 11:50:29" nil "P143000039-PC" "n3-p5-p7ncn.20") | list("[Package] BOTTOM" "399.Pkg to Pkg Spacing" "0 MIL [PACKAGE_HEIGHT_MIN]" "82.68 MIL" "-82.68 MIL" "DRC ERROR CLASS/PACKAGE_BOTTOM" "[Shape] Package Geometry/Place_Bound_Bottom ((7834.5 2672.39) (7859.5 2697.39))" "[Shape] Package Geometry/Place_Bound_Bottom ((7787.95 2676.38) (7982.05 3037.4))" list(7834.500000 2697.390000) nil)@@@list("kelly1_pan" "2015/09/04 16:12:41" nil "P143000035-PC" "n3-p5-p7ncn.20")@@@list("jennifer_hsu" "2015/09/07 11:50:50" nil "P143000039-PC" "n3-p5-p7ncn.20") | list("[Package] BOTTOM" "400.Pkg to Pkg Spacing" "0 MIL [PACKAGE_HEIGHT_MIN]" "82.68 MIL" "-82.68 MIL" "DRC ERROR CLASS/PACKAGE_BOTTOM" "[Shape] Package Geometry/Place_Bound_Bottom ((7873.5 2671.39) (7898.5 2696.39))" "[Shape] Package Geometry/Place_Bound_Bottom ((7787.95 2676.38) (7982.05 3037.4))" list(7873.500000 2696.390000) nil)@@@list("kelly1_pan" "2015/09/04 16:12:42" nil "P143000035-PC" "n3-p5-p7ncn.20")@@@list("jennifer_hsu" "2015/09/07 11:50:51" nil "P143000039-PC" "n3-p5-p7ncn.20") | list("[Electrical] ALL" "244.Diffpair Max Uncoupled Length" "200 MIL [DIFFP_UNCOUPLED_LENGTH]" "214.97 MIL" "-14.97 MIL" "DRC ERROR CLASS/ALL" "[PinPair] <uTiL>cId6845<uTiL>.2:<uTiL>cId7050<uTiL>.1 ((7504.0 1991.34) (8300.0 972.86))" "[PinPair] <uTiL>cId6381<uTiL>.2:<uTiL>cId7049<uTiL>.1 ((7543.0 1991.34) (8300.0 1002.86))" list(8300.000000 1002.860000) nil)@@@list("kelly1_pan" "2015/09/04 14:32:37" nil "P143000035-PC" "n3-p5-p7ncn.20")@@@list("jennifer_hsu" "2015/09/07 11:47:57" nil "P143000039-PC" "n3-p5-p7ncn.20") | list("[Package] BOTTOM" "384.Pkg to Pkg Spacing" "0 MIL [PACKAGE_HEIGHT_MIN]" "27.56 MIL" "-27.56 MIL" "DRC ERROR CLASS/PACKAGE_BOTTOM" "[Shape] Package Geometry/Place_Bound_Bottom ((8404.37 2723.7) (8475.63 2850.08))" "[Shape] Package Geometry/Place_Bound_Bottom ((8396.69 2725.87) (8483.31 2847.91))" list(8404.370000 2725.870000) nil)@@@list("kelly1_pan" "2015/09/04 16:12:25" nil "P143000035-PC" "n3-p5-p7ncn.20")@@@list("jennifer_hsu" "2015/09/07 11:50:36" nil "P143000039-PC" "n3-p5-p7ncn.20") | list("[Electrical] ALL" "250.Propagation Delay" "::0 mil:500 mil [PROPAGATION_DELAY]" "636.58 MIL" "" "DRC ERROR CLASS/ALL" "[PinPair] <uTiL>cId5095<uTiL>.U2:<uTiL>cId5438<uTiL>.D2 ((8517.56 1116.1) (8550.63 1543.15))" " " list(8550.630000 1543.150000) nil)@@@list("kelly1_pan" "2015/09/04 14:32:45" nil "P143000035-PC" "n3-p5-p7ncn.20")@@@list("jennifer_hsu" "2015/09/07 11:48:03" nil "P143000039-PC" "n3-p5-p7ncn.20") | list("[Electrical] ALL" "249.Propagation Delay" "::0 mil:500 mil [PROPAGATION_DELAY]" "566.78 MIL" "" "DRC ERROR CLASS/ALL" "[PinPair] <uTiL>cId5095<uTiL>.U1:<uTiL>cId5438<uTiL>.D1 ((8517.56 1134.21) (8550.63 1523.46))" " " list(8550.630000 1523.460000) nil)@@@list("kelly1_pan" "2015/09/04 14:32:44" nil "P143000035-PC" "n3-p5-p7ncn.20")@@@list("jennifer_hsu" "2015/09/07 11:48:02" nil "P143000039-PC" "n3-p5-p7ncn.20") | list("[Electrical] ALL" "225.Propagation Delay" "::0 mil:3000 mil [PROPAGATION_DELAY]" "3343.14 MIL" "" "DRC ERROR CLASS/ALL" "[PinPair] <uTiL>cId1833<uTiL>.3:<uTiL>cId5095<uTiL>.R1 ((9355.5 3438.98) (8553.78 1134.21))" " " list(8553.780000 1134.210000) nil)@@@list("kelly1_pan" "2015/09/04 14:31:56" nil "P143000035-PC" "n3-p5-p7ncn.20")@@@list("jennifer_hsu" "2015/09/07 11:47:38" nil "P143000039-PC" "n3-p5-p7ncn.20") | list("[Electrical] ALL" "226.Propagation Delay" "::0 mil:3000 mil [PROPAGATION_DELAY]" "3343.48 MIL" "" "DRC ERROR CLASS/ALL" "[PinPair] <uTiL>cId1833<uTiL>.1:<uTiL>cId5095<uTiL>.R2 ((9355.5 3478.35) (8553.78 1116.1))" " " list(8553.780000 1116.100000) nil)@@@list("kelly1_pan" "2015/09/04 14:31:58" nil "P143000035-PC" "n3-p5-p7ncn.20")@@@list("jennifer_hsu" "2015/09/07 11:47:39" nil "P143000039-PC" "n3-p5-p7ncn.20") | list("[Electrical] ALL" "221.Propagation Delay" "::0 mil:3000 mil [PROPAGATION_DELAY]" "3339.38 MIL" "" "DRC ERROR CLASS/ALL" "[PinPair] <uTiL>cId1833<uTiL>.6:<uTiL>cId5095<uTiL>.N1 ((9402.74 3379.92) (8590.0 1134.21))" " " list(8590.000000 1134.210000) nil)@@@list("kelly1_pan" "2015/09/04 14:31:52" nil "P143000035-PC" "n3-p5-p7ncn.20")@@@list("jennifer_hsu" "2015/09/07 11:47:34" nil "P143000039-PC" "n3-p5-p7ncn.20") | list("[Electrical] ALL" "222.Propagation Delay" "::0 mil:3000 mil [PROPAGATION_DELAY]" "3336.68 MIL" "" "DRC ERROR CLASS/ALL" "[PinPair] <uTiL>cId1833<uTiL>.4:<uTiL>cId5095<uTiL>.N2 ((9402.74 3419.29) (8590.0 1116.1))" " " list(8590.000000 1116.100000) nil)@@@list("kelly1_pan" "2015/09/04 14:31:54" nil "P143000035-PC" "n3-p5-p7ncn.20")@@@list("jennifer_hsu" "2015/09/07 11:47:35" nil "P143000039-PC" "n3-p5-p7ncn.20") | list("[Electrical] ALL" "217.Propagation Delay" "::0 mil:3000 mil [PROPAGATION_DELAY]" "3339.99 MIL" "" "DRC ERROR CLASS/ALL" "[PinPair] <uTiL>cId1833<uTiL>.9:<uTiL>cId5095<uTiL>.L1 ((9355.5 3320.87) (8626.22 1134.21))" " " list(8626.220000 1134.210000) nil)@@@list("kelly1_pan" "2015/09/04 14:31:48" nil "P143000035-PC" "n3-p5-p7ncn.20")@@@list("jennifer_hsu" "2015/09/07 11:47:29" nil "P143000039-PC" "n3-p5-p7ncn.20") | list("[Electrical] ALL" "218.Propagation Delay" "::0 mil:3000 mil [PROPAGATION_DELAY]" "3340.81 MIL" "" "DRC ERROR CLASS/ALL" "[PinPair] <uTiL>cId1833<uTiL>.7:<uTiL>cId5095<uTiL>.L2 ((9355.5 3360.24) (8626.22 1116.1))" " " list(8626.220000 1116.100000) nil)@@@list("kelly1_pan" "2015/09/04 14:31:49" nil "P143000035-PC" "n3-p5-p7ncn.20")@@@list("jennifer_hsu" "2015/09/07 11:47:30" nil "P143000039-PC" "n3-p5-p7ncn.20") | list("[Electrical] ALL" "209.Propagation Delay" "::0 mil:3000 mil [PROPAGATION_DELAY]" "3339.69 MIL" "" "DRC ERROR CLASS/ALL" "[PinPair] <uTiL>cId1833<uTiL>.12:<uTiL>cId5095<uTiL>.J1 ((9402.74 3261.81) (8662.44 1134.21))" " " list(8662.440000 1134.210000) nil)@@@list("kelly1_pan" "2015/09/04 14:31:40" nil "P143000035-PC" "n3-p5-p7ncn.20")@@@list("jennifer_hsu" "2015/09/07 11:47:21" nil "P143000039-PC" "n3-p5-p7ncn.20") | list("[Electrical] ALL" "210.Propagation Delay" "::0 mil:3000 mil [PROPAGATION_DELAY]" "3339.17 MIL" "" "DRC ERROR CLASS/ALL" "[PinPair] <uTiL>cId1833<uTiL>.10:<uTiL>cId5095<uTiL>.J2 ((9402.74 3301.18) (8662.44 1116.1))" " " list(8662.440000 1116.100000) nil)@@@list("kelly1_pan" "2015/09/04 14:31:41" nil "P143000035-PC" "n3-p5-p7ncn.20")@@@list("jennifer_hsu" "2015/09/07 11:47:22" nil "P143000039-PC" "n3-p5-p7ncn.20") | list("[Package] TOP" "326.Pkg to Pkg Spacing" "0 MIL [PACKAGE_HEIGHT_MIN]" "31.5 MIL" "-31.50 MIL" "DRC ERROR CLASS/PACKAGE_TOP" "[Shape] Package Geometry/Place_Bound_Top ((8694.01 64.1) (8719.01 89.1))" "[Shape] Package Geometry/Place_Bound_Top ((8649.55 30.23) (8834.21 117.25))" list(8694.010000 64.100000) nil)@@@list("kelly1_pan" "2015/09/04 16:11:20" nil "P143000035-PC" "n3-p5-p7ncn.20")@@@list("jennifer_hsu" "2015/09/07 11:49:41" nil "P143000039-PC" "n3-p5-p7ncn.20") | list("[Package] TOP" "327.Pkg to Pkg Spacing" "0 MIL [PACKAGE_HEIGHT_MIN]" "31.5 MIL" "-31.50 MIL" "DRC ERROR CLASS/PACKAGE_TOP" "[Shape] Package Geometry/Place_Bound_Top ((8764.5 62.5) (8789.5 87.5))" "[Shape] Package Geometry/Place_Bound_Top ((8649.55 30.23) (8834.21 117.25))" list(8764.500000 62.500000) nil)@@@list("kelly1_pan" "2015/09/04 16:11:19" nil "P143000035-PC" "n3-p5-p7ncn.20")@@@list("jennifer_hsu" "2015/09/07 11:49:42" nil "P143000039-PC" "n3-p5-p7ncn.20") | list("[Package] TOP" "323.Pkg to Pkg Spacing" "0 MIL [PACKAGE_HEIGHT_MIN]" "27.56 MIL" "-27.56 MIL" "DRC ERROR CLASS/PACKAGE_TOP" "[Shape] Package Geometry/Place_Bound_Top ((8916.81 2406.26) (9043.19 2477.52))" "[Shape] Package Geometry/Place_Bound_Top ((8920.35 2398.24) (9042.39 2484.86))" list(8920.350000 2406.260000) nil)@@@list("kelly1_pan" "2015/09/04 16:11:14" nil "P143000035-PC" "n3-p5-p7ncn.20")@@@list("jennifer_hsu" "2015/09/07 11:49:29" nil "P143000039-PC" "n3-p5-p7ncn.20") | list("[Package] TOP" "322.Pkg to Pkg Spacing" "0 MIL [PACKAGE_HEIGHT_MIN]" "27.56 MIL" "-27.56 MIL" "DRC ERROR CLASS/PACKAGE_TOP" "[Shape] Package Geometry/Place_Bound_Top ((8918.18 2300.92) (9044.56 2372.18))" "[Shape] Package Geometry/Place_Bound_Top ((8920.35 2293.24) (9042.39 2379.86))" list(8920.350000 2300.920000) nil)@@@list("kelly1_pan" "2015/09/04 16:11:13" nil "P143000035-PC" "n3-p5-p7ncn.20")@@@list("jennifer_hsu" "2015/09/07 11:49:27" nil "P143000039-PC" "n3-p5-p7ncn.20") | list("[Electrical] ALL" "295.Propagation Delay" "::0 mil:2050 mil [PROPAGATION_DELAY]" "2139.28 MIL" "" "DRC ERROR CLASS/ALL" "[PinPair] <uTiL>cId5095<uTiL>.Y2:<uTiL>cId6695<uTiL>.2 ((8463.23 1116.1) (8931.7 2621.9))" " " list(8931.700000 2621.900000) nil)@@@list("kelly1_pan" "2015/09/04 16:10:41" nil "P143000035-PC" "n3-p5-p7ncn.20")@@@list("jennifer_hsu" "2015/09/07 11:48:59" nil "P143000039-PC" "n3-p5-p7ncn.20") | list("[Electrical] ALL" "292.Propagation Delay" "::0 mil:1930 mil [PROPAGATION_DELAY]" "2093.77 MIL" "" "DRC ERROR CLASS/ALL" "[PinPair] <uTiL>cId5095<uTiL>.Y1:<uTiL>cId6694<uTiL>.2 ((8463.23 1134.21) (8931.7 2521.1))" " " list(8931.700000 2521.100000) nil)@@@list("kelly1_pan" "2015/09/04 16:10:37" nil "P143000035-PC" "n3-p5-p7ncn.20")@@@list("jennifer_hsu" "2015/09/07 11:48:56" nil "P143000039-PC" "n3-p5-p7ncn.20") | list("[Package] BOTTOM" "385.Pkg to Pkg Spacing" "0 MIL [PACKAGE_HEIGHT_MIN]" "27.56 MIL" "-27.56 MIL" "DRC ERROR CLASS/PACKAGE_BOTTOM" "[Shape] Package Geometry/Place_Bound_Bottom ((8946.81 5321.26) (9073.19 5392.52))" "[Shape] Package Geometry/Place_Bound_Bottom ((8948.98 5313.58) (9071.02 5400.2))" list(8948.980000 5321.260000) nil)@@@list("kelly1_pan" "2015/09/04 16:12:26" nil "P143000035-PC" "n3-p5-p7ncn.20")@@@list("jennifer_hsu" "2015/09/07 11:50:37" nil "P143000039-PC" "n3-p5-p7ncn.20") | list("[Package] BOTTOM" "388.Pkg to Pkg Spacing" "0 MIL [PACKAGE_HEIGHT_MIN]" "27.56 MIL" "-27.56 MIL" "DRC ERROR CLASS/PACKAGE_BOTTOM" "[Shape] Package Geometry/Place_Bound_Bottom ((8946.81 5196.26) (9073.19 5267.52))" "[Shape] Package Geometry/Place_Bound_Bottom ((8948.98 5188.58) (9071.02 5275.2))" list(8948.980000 5196.260000) nil)@@@list("kelly1_pan" "2015/09/04 16:12:29" nil "P143000035-PC" "n3-p5-p7ncn.20")@@@list("jennifer_hsu" "2015/09/07 11:50:39" nil "P143000039-PC" "n3-p5-p7ncn.20") | list("[Package] BOTTOM" "387.Pkg to Pkg Spacing" "0 MIL [PACKAGE_HEIGHT_MIN]" "27.56 MIL" "-27.56 MIL" "DRC ERROR CLASS/PACKAGE_BOTTOM" "[Shape] Package Geometry/Place_Bound_Bottom ((8946.81 5086.26) (9073.19 5157.52))" "[Shape] Package Geometry/Place_Bound_Bottom ((8948.98 5078.58) (9071.02 5165.2))" list(8948.980000 5086.260000) nil)@@@list("kelly1_pan" "2015/09/04 16:12:28" nil "P143000035-PC" "n3-p5-p7ncn.20")@@@list("jennifer_hsu" "2015/09/07 11:50:38" nil "P143000039-PC" "n3-p5-p7ncn.20") | list("[Package] BOTTOM" "386.Pkg to Pkg Spacing" "0 MIL [PACKAGE_HEIGHT_MIN]" "27.56 MIL" "-27.56 MIL" "DRC ERROR CLASS/PACKAGE_BOTTOM" "[Shape] Package Geometry/Place_Bound_Bottom ((8946.81 4976.26) (9073.19 5047.52))" "[Shape] Package Geometry/Place_Bound_Bottom ((8948.98 4968.58) (9071.02 5055.2))" list(8948.980000 4976.260000) nil)@@@list("kelly1_pan" "2015/09/04 16:12:27" nil "P143000035-PC" "n3-p5-p7ncn.20")@@@list("jennifer_hsu" "2015/09/07 11:50:37" nil "P143000039-PC" "n3-p5-p7ncn.20") | list("[Package] BOTTOM" "367.Pkg to Pkg Spacing" "0 MIL [PACKAGE_HEIGHT_MIN]" "13.78 MIL" "-13.78 MIL" "DRC ERROR CLASS/PACKAGE_BOTTOM" "[Shape] Package Geometry/Place_Bound_Bottom ((8964.8 768.98) (9051.42 891.02))" "[Shape] Package Geometry/Place_Bound_Bottom ((8976.42 777.01) (9039.8 882.99))" list(8976.420000 777.010000) nil)@@@list("kelly1_pan" "2015/09/04 16:12:08" nil "P143000035-PC" "n3-p5-p7ncn.20")@@@list("jennifer_hsu" "2015/09/07 11:50:22" nil "P143000039-PC" "n3-p5-p7ncn.20") | list("[Package] BOTTOM" "389.Pkg to Pkg Spacing" "0 MIL [PACKAGE_HEIGHT_MIN]" "27.56 MIL" "-27.56 MIL" "DRC ERROR CLASS/PACKAGE_BOTTOM" "[Shape] Package Geometry/Place_Bound_Bottom ((8978.81 2433.26) (9105.19 2504.52))" "[Shape] Package Geometry/Place_Bound_Bottom ((8982.35 2425.92) (9104.39 2512.54))" list(8982.350000 2433.260000) nil)@@@list("kelly1_pan" "2015/09/04 16:12:29" nil "P143000035-PC" "n3-p5-p7ncn.20")@@@list("jennifer_hsu" "2015/09/07 11:50:40" nil "P143000039-PC" "n3-p5-p7ncn.20") | list("[Package] TOP" "324.Pkg to Pkg Spacing" "0 MIL [PACKAGE_HEIGHT_MIN]" "27.56 MIL" "-27.56 MIL" "DRC ERROR CLASS/PACKAGE_TOP" "[Shape] Package Geometry/Place_Bound_Top ((9004.31 1440.46) (9130.69 1511.72))" "[Shape] Package Geometry/Place_Bound_Top ((9007.85 1432.44) (9129.89 1519.06))" list(9007.850000 1440.460000) nil)@@@list("kelly1_pan" "2015/09/04 16:11:16" nil "P143000035-PC" "n3-p5-p7ncn.20")@@@list("jennifer_hsu" "2015/09/07 11:49:39" nil "P143000039-PC" "n3-p5-p7ncn.20") | list("[Package] TOP" "325.Pkg to Pkg Spacing" "0 MIL [PACKAGE_HEIGHT_MIN]" "27.56 MIL" "-27.56 MIL" "DRC ERROR CLASS/PACKAGE_TOP" "[Shape] Package Geometry/Place_Bound_Top ((9013.98 1348.42) (9140.36 1419.68))" "[Shape] Package Geometry/Place_Bound_Top ((9016.15 1340.74) (9138.19 1427.36))" list(9016.150000 1348.420000) nil)@@@list("kelly1_pan" "2015/09/04 16:11:17" nil "P143000035-PC" "n3-p5-p7ncn.20")@@@list("jennifer_hsu" "2015/09/07 11:49:40" nil "P143000039-PC" "n3-p5-p7ncn.20") | list("[Package] TOP" "317.Pkg to Place Keepin Spacing" "0 MIL [NONE]" "1115.02 MIL" "-1115.02 MIL" "DRC ERROR CLASS/PACKAGE_TOP" "[Shape] Package Keepin/All ((-897.01 -353.7) (9751.34 6916.7))" "[Shape] Package Geometry/Place_Bound_Top ((8926.59 7055.34) (9116.71 7245.46))" list(9021.640000 5940.320000) nil)@@@list("kelly1_pan" "2015/09/04 16:11:06" nil "P143000035-PC" "n3-p5-p7ncn.20")@@@list("jennifer_hsu" "2015/09/07 11:49:24" nil "P143000039-PC" "n3-p5-p7ncn.20") | list("[Package] TOP" "299.Pkg to Pkg Spacing" "0 MIL [PACKAGE_HEIGHT_MIN]" "23.62 MIL" "-23.62 MIL" "DRC ERROR CLASS/PACKAGE_TOP" "[Shape] Package Geometry/Place_Bound_Top ((9048.98 3518.58) (9171.02 3605.2))" "[Shape] Package Geometry/Place_Bound_Top ((9062.39 3530.2) (9157.61 3593.58))" list(9062.390000 3530.200000) nil)@@@list("kelly1_pan" "2015/09/04 16:10:46" nil "P143000035-PC" "n3-p5-p7ncn.20")@@@list("jennifer_hsu" "2015/09/07 11:49:02" nil "P143000039-PC" "n3-p5-p7ncn.20") | list("[Package] TOP" "298.Pkg to Pkg Spacing" "0 MIL [PACKAGE_HEIGHT_MIN]" "23.62 MIL" "-23.62 MIL" "DRC ERROR CLASS/PACKAGE_TOP" "[Shape] Package Geometry/Place_Bound_Top ((9048.98 3423.58) (9171.02 3510.2))" "[Shape] Package Geometry/Place_Bound_Top ((9062.39 3435.2) (9157.61 3498.58))" list(9062.390000 3435.200000) nil)@@@list("kelly1_pan" "2015/09/04 16:10:45" nil "P143000035-PC" "n3-p5-p7ncn.20")@@@list("jennifer_hsu" "2015/09/07 11:49:02" nil "P143000039-PC" "n3-p5-p7ncn.20") | list("[Package] TOP" "297.Pkg to Pkg Spacing" "0 MIL [PACKAGE_HEIGHT_MIN]" "23.62 MIL" "-23.62 MIL" "DRC ERROR CLASS/PACKAGE_TOP" "[Shape] Package Geometry/Place_Bound_Top ((9048.98 3013.58) (9171.02 3100.2))" "[Shape] Package Geometry/Place_Bound_Top ((9062.39 3025.2) (9157.61 3088.58))" list(9062.390000 3025.200000) nil)@@@list("kelly1_pan" "2015/09/04 16:10:44" nil "P143000035-PC" "n3-p5-p7ncn.20")@@@list("jennifer_hsu" "2015/09/07 11:49:01" nil "P143000039-PC" "n3-p5-p7ncn.20") | list("[Package] TOP" "300.Pkg to Pkg Spacing" "0 MIL [PACKAGE_HEIGHT_MIN]" "23.62 MIL" "-23.62 MIL" "DRC ERROR CLASS/PACKAGE_TOP" "[Shape] Package Geometry/Place_Bound_Top ((9048.98 2898.58) (9171.02 2985.2))" "[Shape] Package Geometry/Place_Bound_Top ((9062.39 2910.2) (9157.61 2973.58))" list(9062.390000 2910.200000) nil)@@@list("kelly1_pan" "2015/09/04 16:10:47" nil "P143000035-PC" "n3-p5-p7ncn.20")@@@list("jennifer_hsu" "2015/09/07 11:49:03" nil "P143000039-PC" "n3-p5-p7ncn.20") | list("[Package] BOTTOM" "366.Pkg to Pkg Spacing" "0 MIL [PACKAGE_HEIGHT_MIN]" "13.78 MIL" "-13.78 MIL" "DRC ERROR CLASS/PACKAGE_BOTTOM" "[Shape] Package Geometry/Place_Bound_Bottom ((9059.8 933.98) (9146.42 1056.02))" "[Shape] Package Geometry/Place_Bound_Bottom ((9071.42 942.01) (9134.8 1047.99))" list(9071.420000 942.010000) nil)@@@list("kelly1_pan" "2015/09/04 16:12:07" nil "P143000035-PC" "n3-p5-p7ncn.20")@@@list("jennifer_hsu" "2015/09/07 11:50:19" nil "P143000039-PC" "n3-p5-p7ncn.20") | list("[Package] BOTTOM" "390.Pkg to Pkg Spacing" "0 MIL [PACKAGE_HEIGHT_MIN]" "27.56 MIL" "-27.56 MIL" "DRC ERROR CLASS/PACKAGE_BOTTOM" "[Shape] Package Geometry/Place_Bound_Bottom ((9100.98 1305.51) (9172.24 1431.89))" "[Shape] Package Geometry/Place_Bound_Bottom ((9093.3 1307.68) (9179.92 1429.72))" list(9100.980000 1307.680000) nil)@@@list("kelly1_pan" "2015/09/04 16:12:31" nil "P143000035-PC" "n3-p5-p7ncn.20")@@@list("jennifer_hsu" "2015/09/07 11:50:41" nil "P143000039-PC" "n3-p5-p7ncn.20") | list("[Package] BOTTOM" "379.Pkg to Place Keepin Spacing" "0 MIL [NONE]" "437.85 MIL" "-437.85 MIL" "DRC ERROR CLASS/PACKAGE_BOTTOM" "[Shape] Package Keepin/All ((-897.01 -353.7) (9751.34 6916.7))" "[Shape] Package Geometry/Place_Bound_Bottom ((9026.59 -603.72) (9216.71 -413.6))" list(9121.640000 24.250000) nil)@@@list("kelly1_pan" "2015/09/04 16:12:20" nil "P143000035-PC" "n3-p5-p7ncn.20")@@@list("jennifer_hsu" "2015/09/07 11:50:31" nil "P143000039-PC" "n3-p5-p7ncn.20") | list("[Package] BOTTOM" "368.Pkg to Pkg Spacing" "0 MIL [PACKAGE_HEIGHT_MIN]" "122.05 MIL" "-122.05 MIL" "DRC ERROR CLASS/PACKAGE_BOTTOM" "[Shape] Package Geometry/Place_Bound_Bottom ((9135.02 5395.02) (9234.98 5494.99))" "[Shape] Package Geometry/Place_Bound_Bottom ((9194.05 4653.79) (9842.71 5495.81))" list(9215.900000 5405.710000) nil)@@@list("kelly1_pan" "2015/09/04 16:12:09" nil "P143000035-PC" "n3-p5-p7ncn.20")@@@list("jennifer_hsu" "2015/09/07 11:50:23" nil "P143000039-PC" "n3-p5-p7ncn.20") | list("[Electrical] ALL" "175.Diffpair Max Uncoupled Length" "200 MIL [DIFFP_UNCOUPLED_LENGTH]" "224.26 MIL" "-24.26 MIL" "DRC ERROR CLASS/ALL" "[PinPair] <uTiL>cId4006<uTiL>.3:<uTiL>cId3004<uTiL>.20 ((9270.86 5135.04) (9000.55 5257.65))" "[PinPair] <uTiL>cId4006<uTiL>.6:<uTiL>cId3004<uTiL>.19 ((9227.56 5014.56) (9000.55 5218.28))" list(9227.560000 5014.560000) nil)@@@list("kelly1_pan" "2015/09/04 14:30:25" nil "P143000035-PC" "n3-p5-p7ncn.20")@@@list("jennifer_hsu" "2015/09/07 11:46:45" nil "P143000039-PC" "n3-p5-p7ncn.20") | list("[Electrical] ALL" "174.Diffpair Max Uncoupled Length" "200 MIL [DIFFP_UNCOUPLED_LENGTH]" "235.8 MIL" "-35.80 MIL" "DRC ERROR CLASS/ALL" "[PinPair] <uTiL>cId4006<uTiL>.6:<uTiL>cId3004<uTiL>.19 ((9227.56 5014.56) (9000.55 5218.28))" "[PinPair] <uTiL>cId4006<uTiL>.3:<uTiL>cId3004<uTiL>.20 ((9270.86 5135.04) (9000.55 5257.65))" list(9270.860000 5135.040000) nil)@@@list("kelly1_pan" "2015/09/04 14:30:24" nil "P143000035-PC" "n3-p5-p7ncn.20")@@@list("jennifer_hsu" "2015/09/07 11:46:45" nil "P143000039-PC" "n3-p5-p7ncn.20") | list("[Electrical] ALL" "239.Diffpair Max Uncoupled Length" "200 MIL [DIFFP_UNCOUPLED_LENGTH]" "286.36 MIL" "-86.36 MIL" "DRC ERROR CLASS/ALL" "[PinPair] <uTiL>cId4004<uTiL>.9:<uTiL>cId71<uTiL>.A12 ((9299.22 2307.09) (5354.26 1872.15))" "[PinPair] <uTiL>cId4004<uTiL>.8:<uTiL>cId71<uTiL>.B12 ((9299.22 2385.83) (5374.26 1872.15))" list(9299.220000 2385.830000) nil)@@@list("kelly1_pan" "2015/09/04 14:32:29" nil "P143000035-PC" "n3-p5-p7ncn.20")@@@list("jennifer_hsu" "2015/09/07 11:47:52" nil "P143000039-PC" "n3-p5-p7ncn.20") | list("[Electrical] ALL" "237.Diffpair Phase Tolerance" "5 mil [DIFFP_PHASE_TOL]" "5.01 MIL" "" "DRC ERROR CLASS/ALL" "[PinPair] <uTiL>cId4004<uTiL>.8:<uTiL>cId71<uTiL>.B12 ((9299.22 2385.83) (5374.26 1872.15))" "[PinPair] <uTiL>cId4004<uTiL>.9:<uTiL>cId71<uTiL>.A12 ((9299.22 2307.09) (5354.26 1872.15))" list(9299.220000 2307.090000) nil)@@@list("kelly1_pan" "2015/09/04 14:32:26" nil "P143000035-PC" "n3-p5-p7ncn.20")@@@list("jennifer_hsu" "2015/09/07 11:47:50" nil "P143000039-PC" "n3-p5-p7ncn.20") | list("[Electrical] ALL" "230.Propagation Delay" "::3000 mil:8000 mil [PROPAGATION_DELAY]" "8242.26 MIL" "" "DRC ERROR CLASS/ALL" "[PinPair] <uTiL>cId71<uTiL>.G13:<uTiL>cId4005<uTiL>.5 ((5464.13 1850.16) (9299.22 1543.31))" " " list(9299.220000 1543.310000) nil)@@@list("kelly1_pan" "2015/09/04 14:32:02" nil "P143000035-PC" "n3-p5-p7ncn.20")@@@list("jennifer_hsu" "2015/09/07 11:47:43" nil "P143000039-PC" "n3-p5-p7ncn.20") | list("[Electrical] ALL" "229.Propagation Delay" "::3000 mil:8000 mil [PROPAGATION_DELAY]" "8242.58 MIL" "" "DRC ERROR CLASS/ALL" "[PinPair] <uTiL>cId71<uTiL>.H13:<uTiL>cId4005<uTiL>.6 ((5494.13 1848.16) (9299.22 1464.57))" " " list(9299.220000 1464.570000) nil)@@@list("kelly1_pan" "2015/09/04 14:32:01" nil "P143000035-PC" "n3-p5-p7ncn.20")@@@list("jennifer_hsu" "2015/09/07 11:47:42" nil "P143000039-PC" "n3-p5-p7ncn.20") | list("[Electrical] ALL" "232.Diffpair Max Uncoupled Length" "200 MIL [DIFFP_UNCOUPLED_LENGTH]" "224.08 MIL" "-24.08 MIL" "DRC ERROR CLASS/ALL" "[PinPair] <uTiL>cId4005<uTiL>.9:<uTiL>cId71<uTiL>.C14 ((9299.22 1228.35) (5397.06 1827.13))" "[PinPair] <uTiL>cId4005<uTiL>.8:<uTiL>cId71<uTiL>.B14 ((9299.22 1307.09) (5377.06 1827.13))" list(9299.220000 1307.090000) nil)@@@list("kelly1_pan" "2015/09/04 14:32:04" nil "P143000035-PC" "n3-p5-p7ncn.20")@@@list("jennifer_hsu" "2015/09/07 11:47:45" nil "P143000039-PC" "n3-p5-p7ncn.20") | list("[Package] TOP" "318.Pkg to Place Keepin Spacing" "0 MIL [NONE]" "437.85 MIL" "-437.85 MIL" "DRC ERROR CLASS/PACKAGE_TOP" "[Shape] Package Keepin/All ((-897.01 -353.7) (9751.34 6916.7))" "[Shape] Package Geometry/Place_Bound_Top ((9226.59 -603.72) (9416.71 -413.6))" list(9321.660000 24.250000) nil)@@@list("kelly1_pan" "2015/09/04 16:11:07" nil "P143000035-PC" "n3-p5-p7ncn.20")@@@list("jennifer_hsu" "2015/09/07 11:49:25" nil "P143000039-PC" "n3-p5-p7ncn.20") | list("[Electrical] ALL" "224.Diffpair Max Uncoupled Length" "200 MIL [DIFFP_UNCOUPLED_LENGTH]" "243.42 MIL" "-43.42 MIL" "DRC ERROR CLASS/ALL" "[PinPair] <uTiL>cId1833<uTiL>.3:<uTiL>cId5095<uTiL>.R1 ((9355.5 3438.98) (8553.78 1134.21))" "[PinPair] <uTiL>cId1833<uTiL>.1:<uTiL>cId5095<uTiL>.R2 ((9355.5 3478.35) (8553.78 1116.1))" list(9355.500000 3478.350000) nil)@@@list("kelly1_pan" "2015/09/04 14:31:55" nil "P143000035-PC" "n3-p5-p7ncn.20")@@@list("jennifer_hsu" "2015/09/07 11:47:37" nil "P143000039-PC" "n3-p5-p7ncn.20") | list("[Electrical] ALL" "216.Diffpair Max Uncoupled Length" "200 MIL [DIFFP_UNCOUPLED_LENGTH]" "252.9 MIL" "-52.90 MIL" "DRC ERROR CLASS/ALL" "[PinPair] <uTiL>cId1833<uTiL>.9:<uTiL>cId5095<uTiL>.L1 ((9355.5 3320.87) (8626.22 1134.21))" "[PinPair] <uTiL>cId1833<uTiL>.7:<uTiL>cId5095<uTiL>.L2 ((9355.5 3360.24) (8626.22 1116.1))" list(9355.500000 3360.240000) nil)@@@list("kelly1_pan" "2015/09/04 14:31:46" nil "P143000035-PC" "n3-p5-p7ncn.20")@@@list("jennifer_hsu" "2015/09/07 11:47:28" nil "P143000039-PC" "n3-p5-p7ncn.20") | list("[Electrical] ALL" "288.Propagation Delay" "::0.00 MIL:950.00 MIL [PROPAGATION_DELAY]" "1058.32 MIL" "" "DRC ERROR CLASS/ALL" "[PinPair] <uTiL>cId3555<uTiL>.2:<uTiL>cId1833<uTiL>.15 ((8891.0 2619.0) (9355.5 3202.75))" " " list(9355.500000 3202.750000) nil)@@@list("kelly1_pan" "2015/09/04 16:10:31" nil "P143000035-PC" "n3-p5-p7ncn.20")@@@list("jennifer_hsu" "2015/09/07 11:48:44" nil "P143000039-PC" "n3-p5-p7ncn.20") | list("[Electrical] ALL" "220.Diffpair Max Uncoupled Length" "200 MIL [DIFFP_UNCOUPLED_LENGTH]" "289.87 MIL" "-89.87 MIL" "DRC ERROR CLASS/ALL" "[PinPair] <uTiL>cId1833<uTiL>.6:<uTiL>cId5095<uTiL>.N1 ((9402.74 3379.92) (8590.0 1134.21))" "[PinPair] <uTiL>cId1833<uTiL>.4:<uTiL>cId5095<uTiL>.N2 ((9402.74 3419.29) (8590.0 1116.1))" list(9402.740000 3419.290000) nil)@@@list("kelly1_pan" "2015/09/04 14:31:51" nil "P143000035-PC" "n3-p5-p7ncn.20")@@@list("jennifer_hsu" "2015/09/07 11:47:32" nil "P143000039-PC" "n3-p5-p7ncn.20") | list("[Electrical] ALL" "208.Diffpair Max Uncoupled Length" "200 MIL [DIFFP_UNCOUPLED_LENGTH]" "299.7 MIL" "-99.70 MIL" "DRC ERROR CLASS/ALL" "[PinPair] <uTiL>cId1833<uTiL>.12:<uTiL>cId5095<uTiL>.J1 ((9402.74 3261.81) (8662.44 1134.21))" "[PinPair] <uTiL>cId1833<uTiL>.10:<uTiL>cId5095<uTiL>.J2 ((9402.74 3301.18) (8662.44 1116.1))" list(9402.740000 3301.180000) nil)@@@list("kelly1_pan" "2015/09/04 14:31:38" nil "P143000035-PC" "n3-p5-p7ncn.20")@@@list("jennifer_hsu" "2015/09/07 11:47:20" nil "P143000039-PC" "n3-p5-p7ncn.20") | list("[Electrical] ALL" "291.Propagation Delay" "::0.00 MIL:1070.00 MIL [PROPAGATION_DELAY]" "1094 MIL" "" "DRC ERROR CLASS/ALL" "[PinPair] <uTiL>cId3556<uTiL>.2:<uTiL>cId1833<uTiL>.16 ((8890.0 2514.89) (9402.74 3183.07))" " " list(9402.740000 3183.070000) nil)@@@list("kelly1_pan" "2015/09/04 16:10:35" nil "P143000035-PC" "n3-p5-p7ncn.20")@@@list("jennifer_hsu" "2015/09/07 11:48:56" nil "P143000039-PC" "n3-p5-p7ncn.20") | list("[Package] BOTTOM" "348.Pkg to Place Keepout Spacing" "0 MIL [PACKAGE_HEIGHT_MIN]" "12.6 MIL" "-12.60 MIL" "DRC ERROR CLASS/PACKAGE_BOTTOM" "[Shape] Package Keepout/Bottom ((9410.87 357.72) (9833.62 906.06))" "[Shape] Package Geometry/Place_Bound_Bottom ((9446.09 711.18) (9481.91 758.82))" list(9446.090000 711.180000) nil)@@@list("kelly1_pan" "2015/09/04 16:11:46" nil "P143000035-PC" "n3-p5-p7ncn.20")@@@list("jennifer_hsu" "2015/09/07 11:49:59" nil "P143000039-PC" "n3-p5-p7ncn.20") | list("[Package] BOTTOM" "349.Pkg to Place Keepout Spacing" "0 MIL [PACKAGE_HEIGHT_MIN]" "12.6 MIL" "-12.60 MIL" "DRC ERROR CLASS/PACKAGE_BOTTOM" "[Shape] Package Keepout/Bottom ((9410.87 357.72) (9833.62 906.06))" "[Shape] Package Geometry/Place_Bound_Bottom ((9446.09 661.18) (9481.91 708.82))" list(9446.090000 701.490000) nil)@@@list("kelly1_pan" "2015/09/04 16:11:47" nil "P143000035-PC" "n3-p5-p7ncn.20")@@@list("jennifer_hsu" "2015/09/07 11:50:00" nil "P143000039-PC" "n3-p5-p7ncn.20") | list("[Package] BOTTOM" "360.Pkg to Place Keepout Spacing" "0 MIL [PACKAGE_HEIGHT_MIN]" "12.99 MIL" "-12.99 MIL" "DRC ERROR CLASS/PACKAGE_BOTTOM" "[Shape] Package Keepout/Bottom ((9410.87 357.72) (9833.62 906.06))" "[Shape] Package Geometry/Place_Bound_Bottom ((9501.02 561.02) (9548.98 588.98))" list(9501.020000 584.270000) nil)@@@list("kelly1_pan" "2015/09/04 16:12:01" nil "P143000035-PC" "n3-p5-p7ncn.20")@@@list("jennifer_hsu" "2015/09/07 11:50:14" nil "P143000039-PC" "n3-p5-p7ncn.20") | list("[Package] BOTTOM" "358.Pkg to Place Keepout Spacing" "0 MIL [PACKAGE_HEIGHT_MIN]" "12.99 MIL" "-12.99 MIL" "DRC ERROR CLASS/PACKAGE_BOTTOM" "[Shape] Package Keepout/Bottom ((9410.87 357.72) (9833.62 906.06))" "[Shape] Package Geometry/Place_Bound_Bottom ((9501.02 591.02) (9548.98 618.98))" list(9501.700000 591.020000) nil)@@@list("kelly1_pan" "2015/09/04 16:11:59" nil "P143000035-PC" "n3-p5-p7ncn.20")@@@list("jennifer_hsu" "2015/09/07 11:50:13" nil "P143000039-PC" "n3-p5-p7ncn.20") | list("[Package] BOTTOM" "361.Pkg to Place Keepout Spacing" "0 MIL [PACKAGE_HEIGHT_MIN]" "12.99 MIL" "-12.99 MIL" "DRC ERROR CLASS/PACKAGE_BOTTOM" "[Shape] Package Keepout/Bottom ((9410.87 357.72) (9833.62 906.06))" "[Shape] Package Geometry/Place_Bound_Bottom ((9501.02 641.02) (9548.98 668.98))" list(9501.710000 641.020000) nil)@@@list("kelly1_pan" "2015/09/04 16:12:02" nil "P143000035-PC" "n3-p5-p7ncn.20")@@@list("jennifer_hsu" "2015/09/07 11:50:15" nil "P143000039-PC" "n3-p5-p7ncn.20") | list("[Package] BOTTOM" "359.Pkg to Place Keepout Spacing" "0 MIL [PACKAGE_HEIGHT_MIN]" "12.99 MIL" "-12.99 MIL" "DRC ERROR CLASS/PACKAGE_BOTTOM" "[Shape] Package Keepout/Bottom ((9410.87 357.72) (9833.62 906.06))" "[Shape] Package Geometry/Place_Bound_Bottom ((9501.02 671.02) (9548.98 698.98))" list(9501.830000 671.020000) nil)@@@list("kelly1_pan" "2015/09/04 16:12:00" nil "P143000035-PC" "n3-p5-p7ncn.20")@@@list("jennifer_hsu" "2015/09/07 11:50:13" nil "P143000039-PC" "n3-p5-p7ncn.20") | list("[Electrical] ALL" "243.Diffpair Max Uncoupled Length" "200 MIL [DIFFP_UNCOUPLED_LENGTH]" "228.72 MIL" "-28.72 MIL" "DRC ERROR CLASS/ALL" "[PinPair] <uTiL>cId6173<uTiL>.A10:<uTiL>cId5095<uTiL>.B15 ((9546.45 700.79) (8789.21 880.67))" "[PinPair] <uTiL>cId6173<uTiL>.A11:<uTiL>cId5095<uTiL>.A15 ((9546.45 720.47) (8807.32 880.67))" list(9546.450000 720.470000) nil)@@@list("kelly1_pan" "2015/09/04 14:32:36" nil "P143000035-PC" "n3-p5-p7ncn.20")@@@list("jennifer_hsu" "2015/09/07 11:47:56" nil "P143000039-PC" "n3-p5-p7ncn.20") | list("[Package] BOTTOM" "369.Pkg to Place Keepin Spacing" "0 MIL [NONE]" "0 MIL" "0.00 MIL" "DRC ERROR CLASS/PACKAGE_BOTTOM" "[Shape] Package Keepin/All ((-897.01 -353.7) (9751.34 6916.7))" "[Shape] Package Geometry/Place_Bound_Bottom ((9194.05 4653.79) (9842.71 5495.81))" list(9602.630000 5441.580000) nil)@@@list("kelly1_pan" "2015/09/04 16:12:10" nil "P143000035-PC" "n3-p5-p7ncn.20")@@@list("jennifer_hsu" "2015/09/07 11:50:23" nil "P143000039-PC" "n3-p5-p7ncn.20") | list("[Package] BOTTOM" "373.Pkg to Place Keepin Spacing" "0 MIL [NONE]" "1130.69 MIL" "-1130.69 MIL" "DRC ERROR CLASS/PACKAGE_BOTTOM" "[Shape] Package Keepin/All ((-897.01 -353.7) (9751.34 6916.7))" "[Shape] Package Geometry/Place_Bound_Bottom ((9591.65 7070.4) (9751.65 7230.4))" list(9633.230000 5940.320000) nil)@@@list("kelly1_pan" "2015/09/04 16:12:14" nil "P143000035-PC" "n3-p5-p7ncn.20")@@@list("jennifer_hsu" "2015/09/07 11:50:26" nil "P143000039-PC" "n3-p5-p7ncn.20") | list("[Package] TOP" "312.Pkg to Place Keepin Spacing" "0 MIL [NONE]" "1130.69 MIL" "-1130.69 MIL" "DRC ERROR CLASS/PACKAGE_TOP" "[Shape] Package Keepin/All ((-897.01 -353.7) (9751.34 6916.7))" "[Shape] Package Geometry/Place_Bound_Top ((9591.65 7070.4) (9751.65 7230.4))" list(9633.230000 5940.320000) nil)@@@list("kelly1_pan" "2015/09/04 16:10:59" nil "P143000035-PC" "n3-p5-p7ncn.20")@@@list("jennifer_hsu" "2015/09/07 11:49:20" nil "P143000039-PC" "n3-p5-p7ncn.20") | list("[Package] TOP" "303.Pkg to Place Keepin Spacing" "0 MIL [NONE]" "0 MIL" "0.00 MIL" "DRC ERROR CLASS/PACKAGE_TOP" "[Shape] Package Keepin/All ((-897.01 -353.7) (9751.34 6916.7))" "[Shape] Package Geometry/Place_Bound_Top ((9264.71 2124.51) (9842.72 2804.63))" list(9648.980000 2128.380000) nil)@@@list("kelly1_pan" "2015/09/04 16:10:49" nil "P143000035-PC" "n3-p5-p7ncn.20")@@@list("jennifer_hsu" "2015/09/07 11:49:05" nil "P143000039-PC" "n3-p5-p7ncn.20") | list("[Package] BOTTOM" "365.Pkg to Place Keepin Spacing" "0 MIL [NONE]" "0 MIL" "0.00 MIL" "DRC ERROR CLASS/PACKAGE_BOTTOM" "[Shape] Package Keepin/All ((-897.01 -353.7) (9751.34 6916.7))" "[Shape] Package Geometry/Place_Bound_Bottom ((9336.61 1757.88) (9671.25 2092.52))" list(9648.980000 1757.880000) nil)@@@list("kelly1_pan" "2015/09/04 16:12:05" nil "P143000035-PC" "n3-p5-p7ncn.20")@@@list("jennifer_hsu" "2015/09/07 11:50:18" nil "P143000039-PC" "n3-p5-p7ncn.20") | list("[Package] TOP" "311.Pkg to Place Keepin Spacing" "0 MIL [NONE]" "0 MIL" "0.00 MIL" "DRC ERROR CLASS/PACKAGE_TOP" "[Shape] Package Keepin/All ((-897.01 -353.7) (9751.34 6916.7))" "[Shape] Package Geometry/Place_Bound_Top ((9251.96 1757.88) (9671.25 2092.52))" list(9648.980000 1757.880000) nil)@@@list("kelly1_pan" "2015/09/04 16:10:57" nil "P143000035-PC" "n3-p5-p7ncn.20")@@@list("jennifer_hsu" "2015/09/07 11:49:19" nil "P143000039-PC" "n3-p5-p7ncn.20") | list("[Package] TOP" "302.Pkg to Place Keepin Spacing" "0 MIL [NONE]" "0 MIL" "0.00 MIL" "DRC ERROR CLASS/PACKAGE_TOP" "[Shape] Package Keepin/All ((-897.01 -353.7) (9751.34 6916.7))" "[Shape] Package Geometry/Place_Bound_Top ((9264.71 1045.77) (9842.72 1725.89))" list(9648.980000 1049.640000) nil)@@@list("kelly1_pan" "2015/09/04 16:10:48" nil "P143000035-PC" "n3-p5-p7ncn.20")@@@list("jennifer_hsu" "2015/09/07 11:49:04" nil "P143000039-PC" "n3-p5-p7ncn.20") | list("[Package] TOP" "301.Pkg to Place Keepin Spacing" "0 MIL [NONE]" "0 MIL" "0.00 MIL" "DRC ERROR CLASS/PACKAGE_TOP" "[Shape] Package Keepin/All ((-897.01 -353.7) (9751.34 6916.7))" "[Shape] Package Geometry/Place_Bound_Top ((9245.47 3771.13) (9883.66 4650.11))" list(9669.470000 3830.080000) nil)@@@list("kelly1_pan" "2015/09/04 16:10:48" nil "P143000035-PC" "n3-p5-p7ncn.20")@@@list("jennifer_hsu" "2015/09/07 11:49:04" nil "P143000039-PC" "n3-p5-p7ncn.20") | list("[Package] BOTTOM" "374.Pkg to Place Keepin Spacing" "0 MIL [NONE]" "452.91 MIL" "-452.91 MIL" "DRC ERROR CLASS/PACKAGE_BOTTOM" "[Shape] Package Keepin/All ((-897.01 -353.7) (9751.34 6916.7))" "[Shape] Package Geometry/Place_Bound_Bottom ((9591.65 -588.66) (9751.65 -428.66))" list(9671.650000 24.250000) nil)@@@list("kelly1_pan" "2015/09/04 16:12:15" nil "P143000035-PC" "n3-p5-p7ncn.20")@@@list("jennifer_hsu" "2015/09/07 11:50:27" nil "P143000039-PC" "n3-p5-p7ncn.20") | list("[Package] TOP" "313.Pkg to Place Keepin Spacing" "0 MIL [NONE]" "452.91 MIL" "-452.91 MIL" "DRC ERROR CLASS/PACKAGE_TOP" "[Shape] Package Keepin/All ((-897.01 -353.7) (9751.34 6916.7))" "[Shape] Package Geometry/Place_Bound_Top ((9591.65 -588.66) (9751.65 -428.66))" list(9671.650000 24.250000) nil)@@@list("kelly1_pan" "2015/09/04 16:11:00" nil "P143000035-PC" "n3-p5-p7ncn.20")@@@list("jennifer_hsu" "2015/09/07 11:49:21" nil "P143000039-PC" "n3-p5-p7ncn.20") | list("[Package] TOP" "305.Pkg to Place Keepin Spacing" "0 MIL [NONE]" "0 MIL" "0.00 MIL" "DRC ERROR CLASS/PACKAGE_TOP" "[Shape] Package Keepin/All ((-897.01 -353.7) (9751.34 6916.7))" "[Shape] Package Geometry/Place_Bound_Top ((9312.78 2911.84) (9842.7 3690.52))" list(9678.500000 2911.840000) nil)@@@list("kelly1_pan" "2015/09/04 16:10:51" nil "P143000035-PC" "n3-p5-p7ncn.20")@@@list("jennifer_hsu" "2015/09/07 11:49:07" nil "P143000039-PC" "n3-p5-p7ncn.20") | list("[Package] TOP" "347.Pkg to Place Keepin Spacing" "0 MIL [NONE]" "0 MIL" "0.00 MIL" "DRC ERROR CLASS/PACKAGE_TOP" "[Shape] Package Keepin/All ((-897.01 -353.7) (9751.34 6916.7))" "[Shape] Package Geometry/Place_Bound_Top ((9478.86 425.72) (9874.4 838.06))" list(9751.340000 429.730000) nil)@@@list("kelly1_pan" "2015/09/04 16:11:44" nil "P143000035-PC" "n3-p5-p7ncn.20")@@@list("jennifer_hsu" "2015/09/07 11:49:58" nil "P143000039-PC" "n3-p5-p7ncn.20") | list("[Package] TOP" "310.Pkg to Place Keepin Spacing" "0 MIL [NONE]" "0 MIL" "0.00 MIL" "DRC ERROR CLASS/PACKAGE_TOP" "[Shape] Package Keepin/All ((-897.01 -353.7) (9751.34 6916.7))" "[Shape] Package Geometry/Place_Bound_Top ((9438.97 5.9) (9773.61 356.3))" list(9751.340000 356.300000) nil)@@@list("kelly1_pan" "2015/09/04 16:10:56" nil "P143000035-PC" "n3-p5-p7ncn.20")@@@list("jennifer_hsu" "2015/09/07 11:49:19" nil "P143000039-PC" "n3-p5-p7ncn.20") | list("[Package] BOTTOM" "364.Pkg to Place Keepin Spacing" "0 MIL [NONE]" "0 MIL" "0.00 MIL" "DRC ERROR CLASS/PACKAGE_BOTTOM" "[Shape] Package Keepin/All ((-897.01 -353.7) (9751.34 6916.7))" "[Shape] Package Geometry/Place_Bound_Bottom ((9448.81 23.62) (9763.77 338.58))" list(9751.340000 119.780000) nil)@@@list("kelly1_pan" "2015/09/04 16:12:05" nil "P143000035-PC" "n3-p5-p7ncn.20")@@@list("jennifer_hsu" "2015/09/07 11:50:18" nil "P143000039-PC" "n3-p5-p7ncn.20") | FIGURE | SIZE | 8.0 | 10.0 | 12.0 | 16.0 | 18.0 | 19.0 | 21.0 | 26.0 | 27.0 | 28.0 | 29.0 | 118.0 | 146.0 | 30.0 | 34.0 | 36.0 | 40.0 | 41.0 | 43.0 | 49.0 | 53.0 | 63.0 | 79.0 | 91.0 | 102.0 | 160.0 | 32.0x18.0 | 41.0x18.0 | 57.0x18.0 | 63.0x24.0 | 72.0x30.0 | 77.0x22.0 | 94.0x28.0 | 101.0x22.0 | 102.0x63.0 | 122.0x102.0 | 134.0x102.0 | DRILL CHART: TOP to BOTTOM (1 to 10) | ALL UNITS ARE IN MILS | TOLERANCE | +3.0/-3.0 | +2.0/-2.0 | PLATED | NON-PLATED | ROTATION | - | 90.000 | 0.000 | QTY | 3375 | 5226 | 44 | 12 | 1241 | 19 | 20 | 6 | 8 | 7 | 18 | 9 | 2 | 4 | 3 | 1 | 10073 | TOTAL HOLES:
